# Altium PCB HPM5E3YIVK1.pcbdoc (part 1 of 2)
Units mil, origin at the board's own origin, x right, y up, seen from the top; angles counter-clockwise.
Board outline 3937 x 3149.7 mil, 6 copper layers (Top Layer, Inner1, Inner2, Inner3, Inner4, Bottom Layer), stack 60.7 mil thick; 242 components, 203 nets, 838 pads, 137 vias.
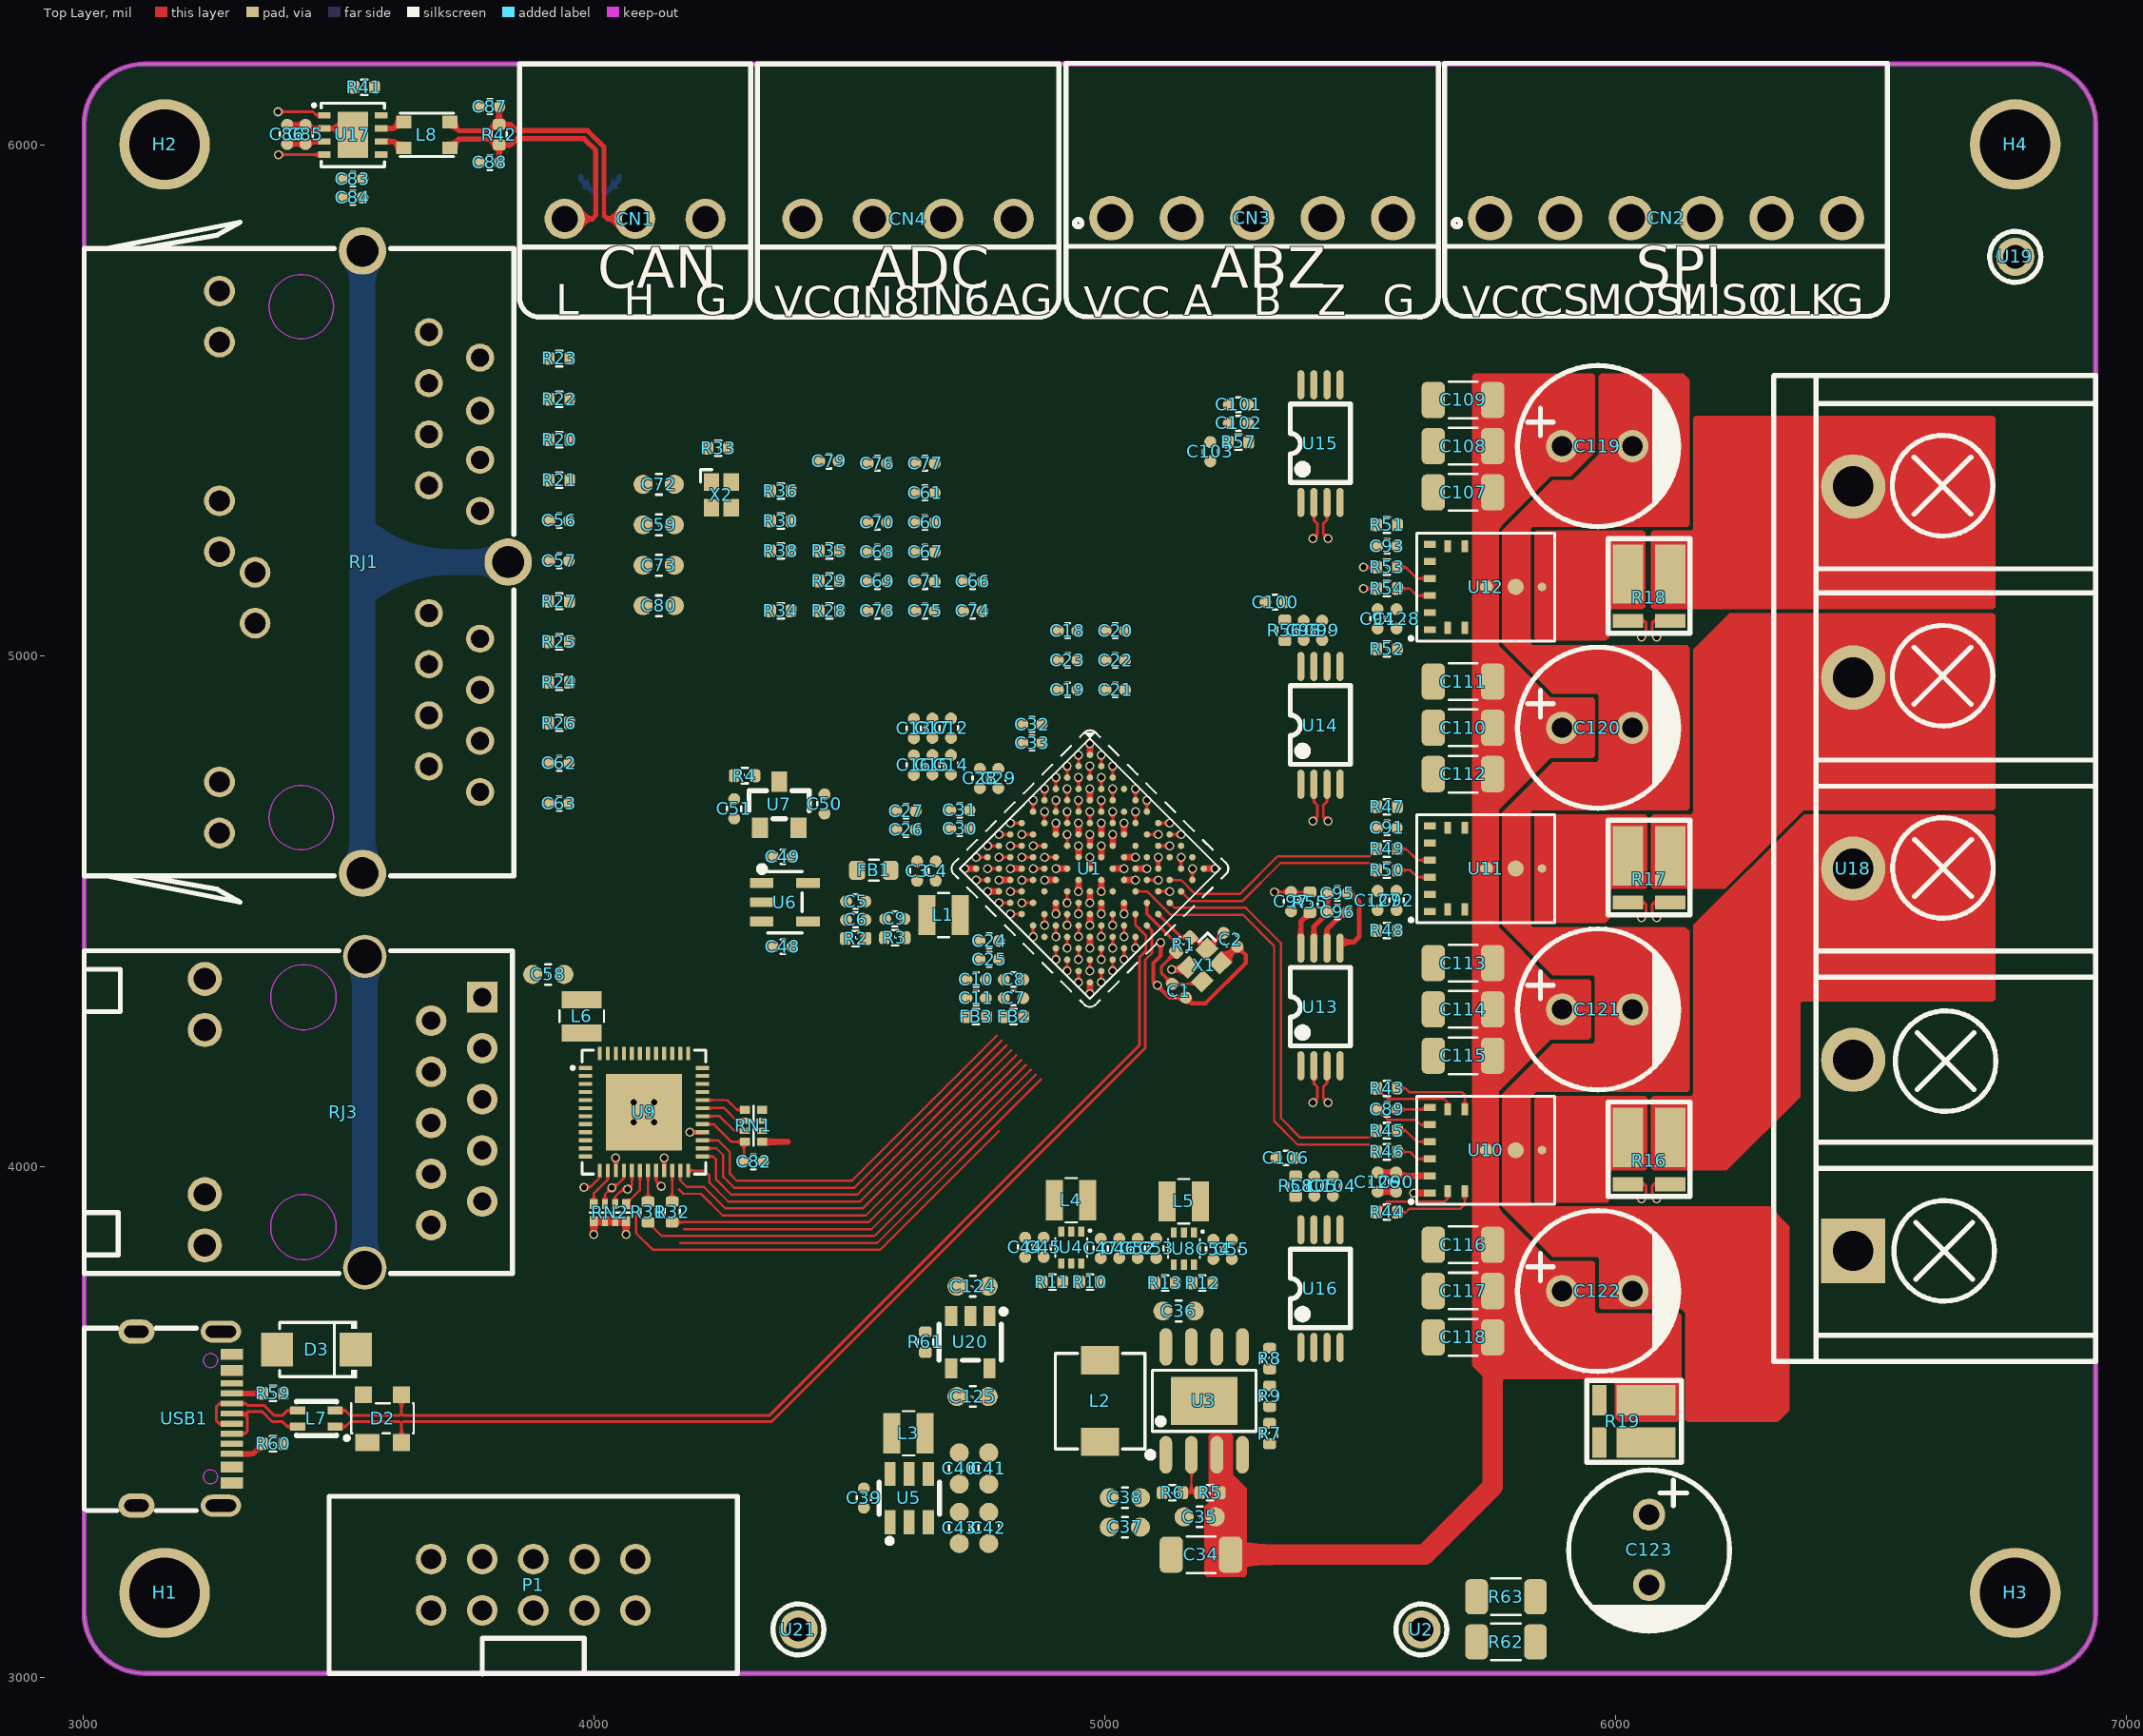
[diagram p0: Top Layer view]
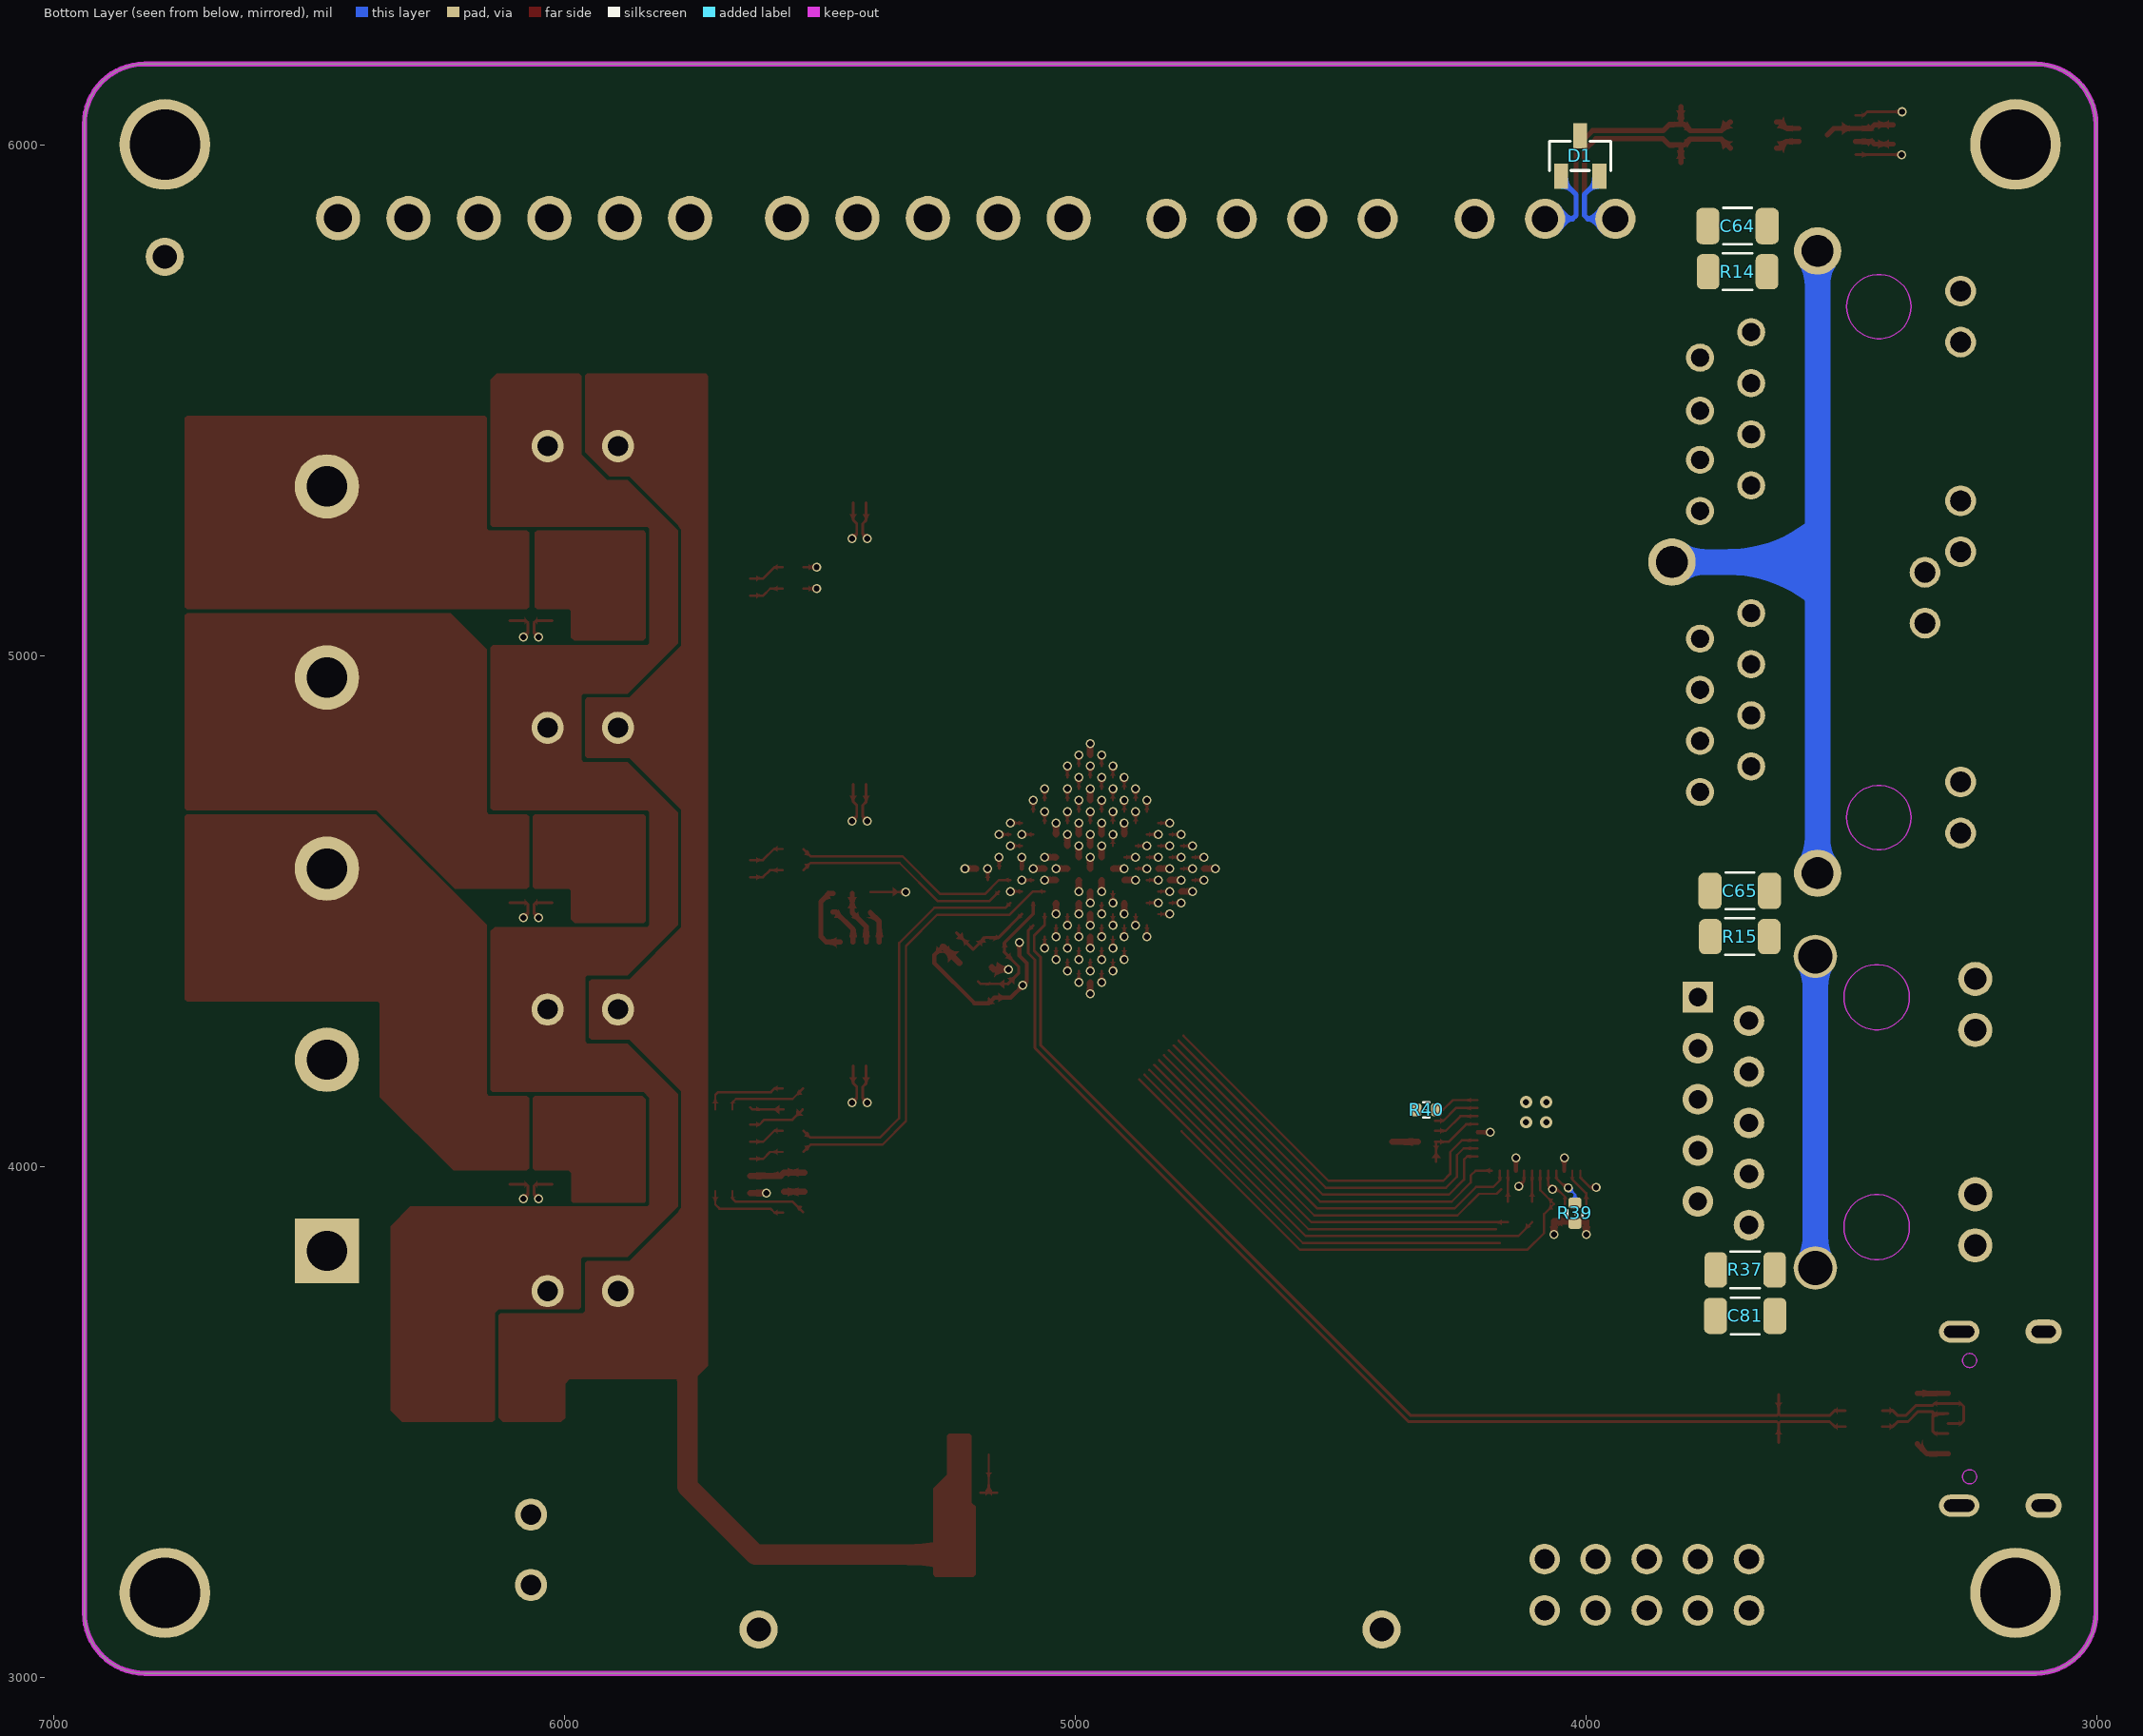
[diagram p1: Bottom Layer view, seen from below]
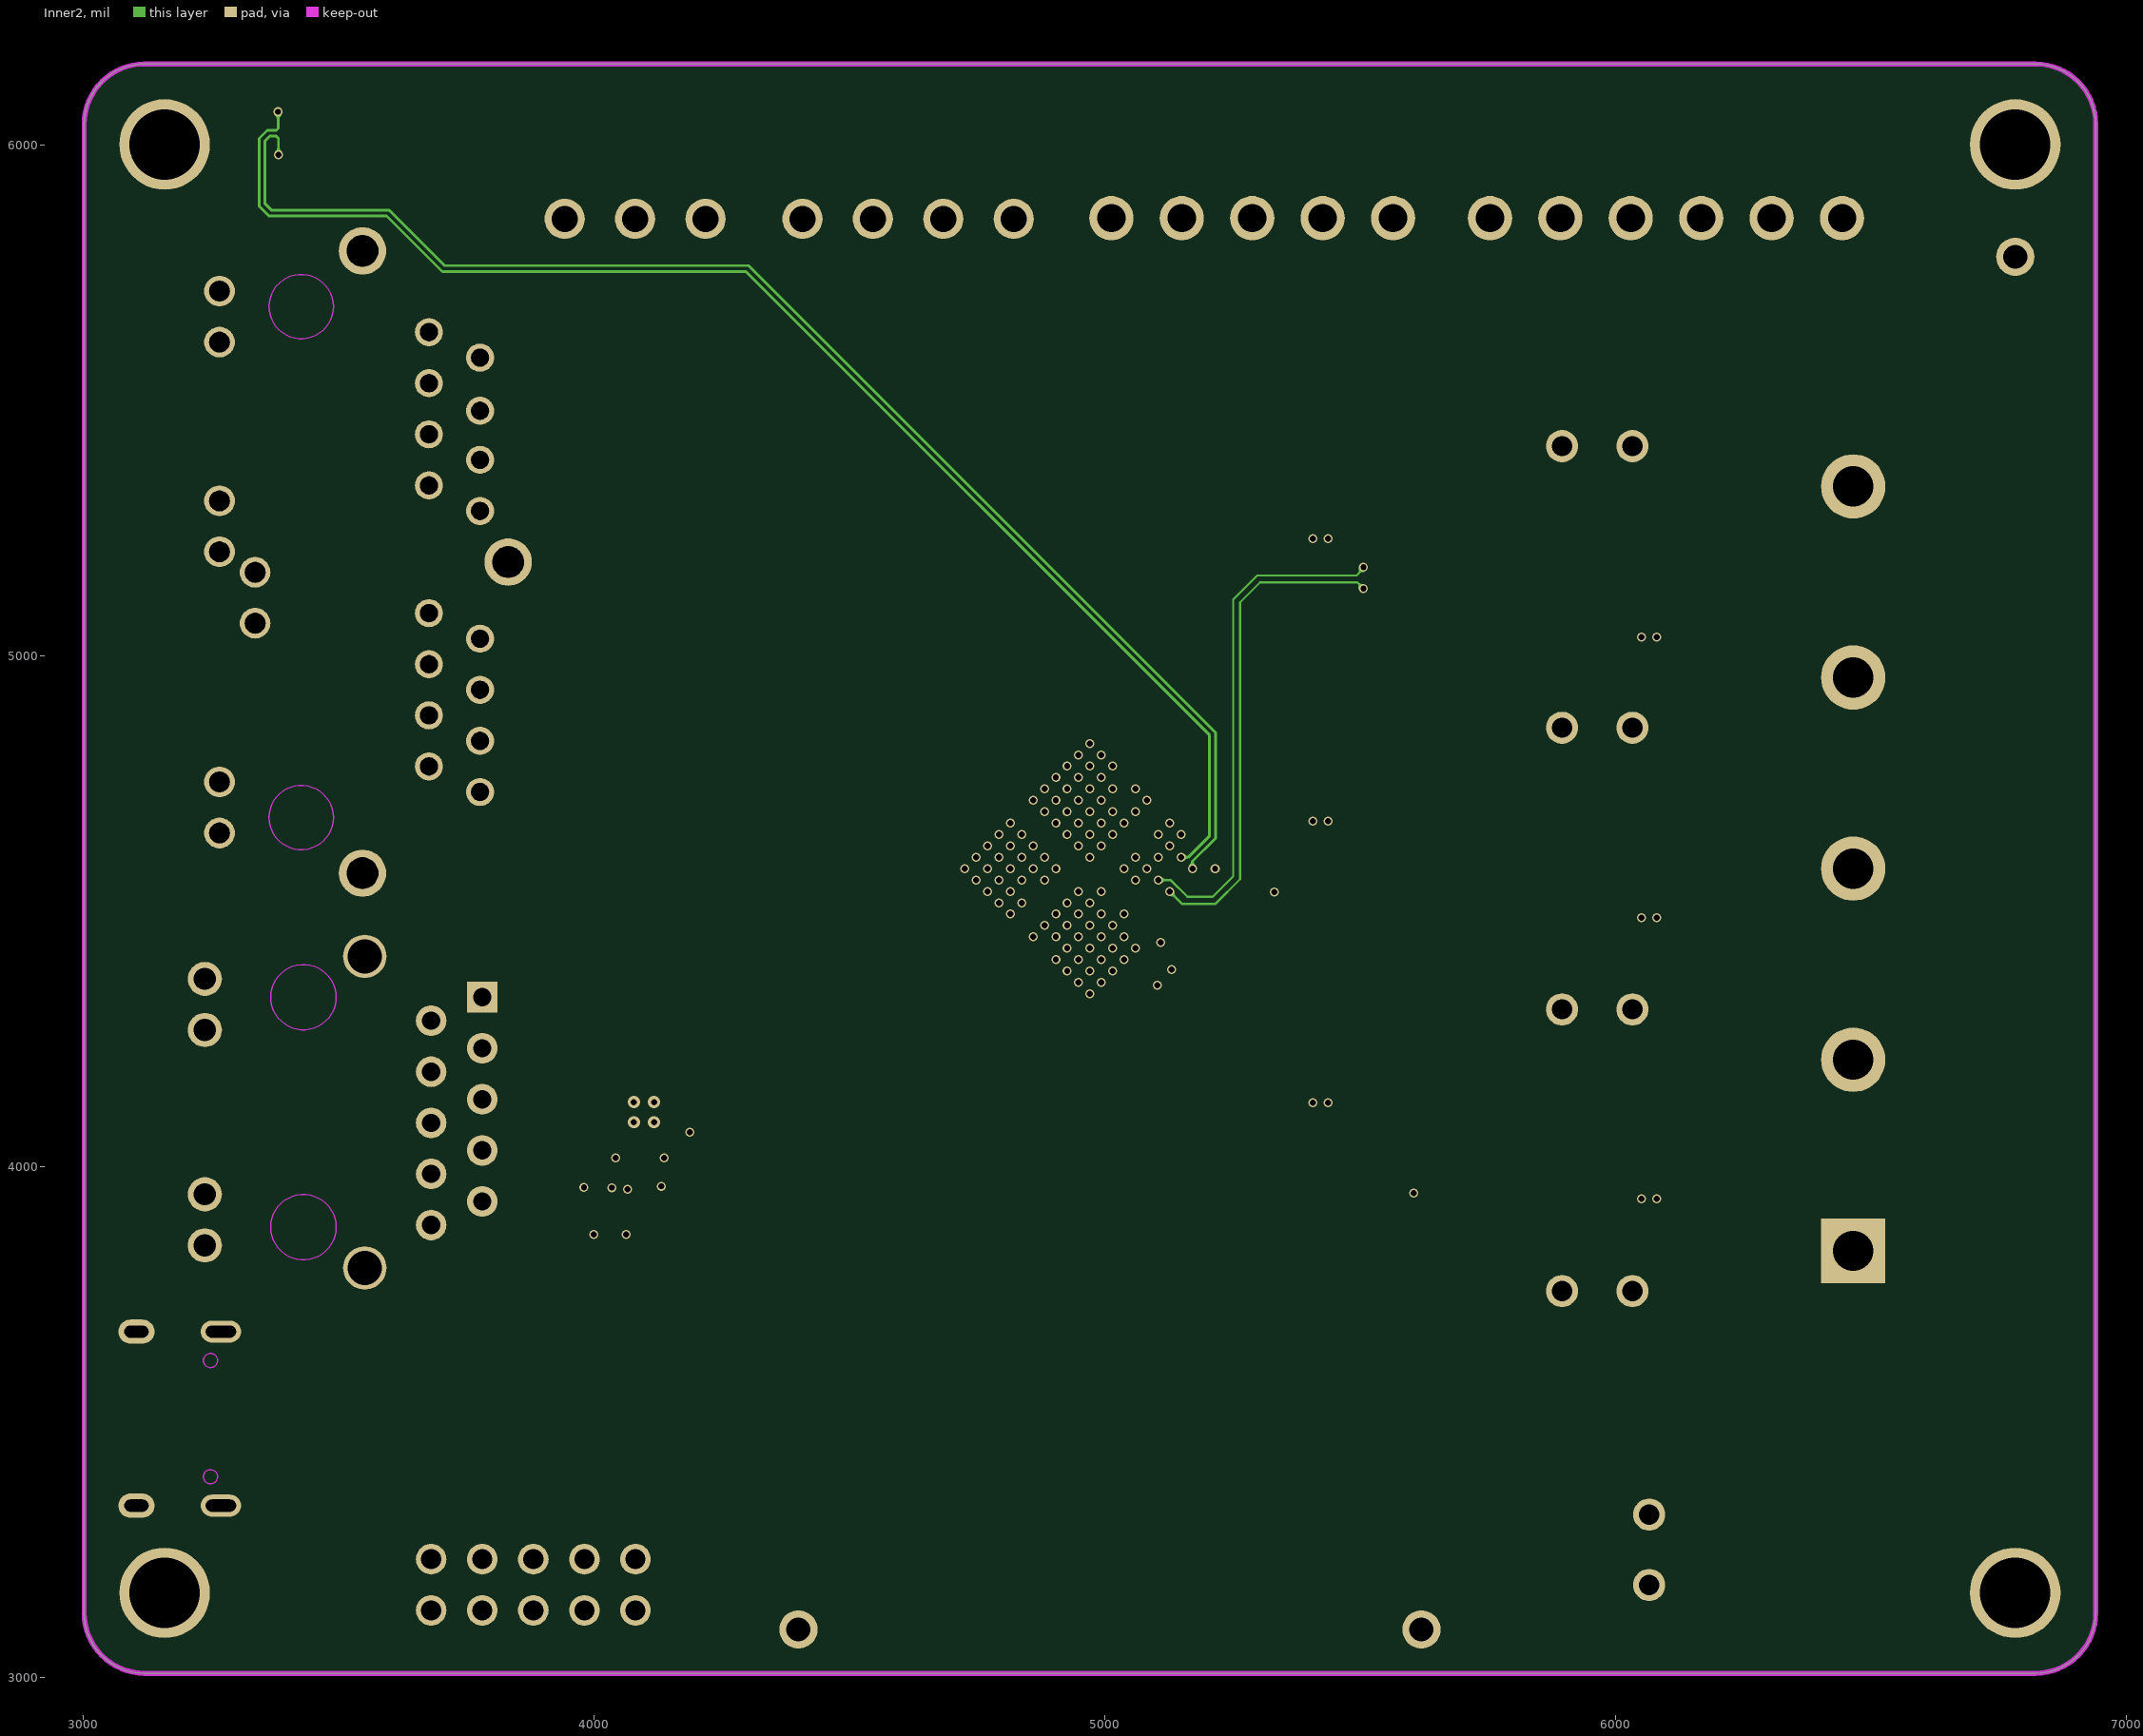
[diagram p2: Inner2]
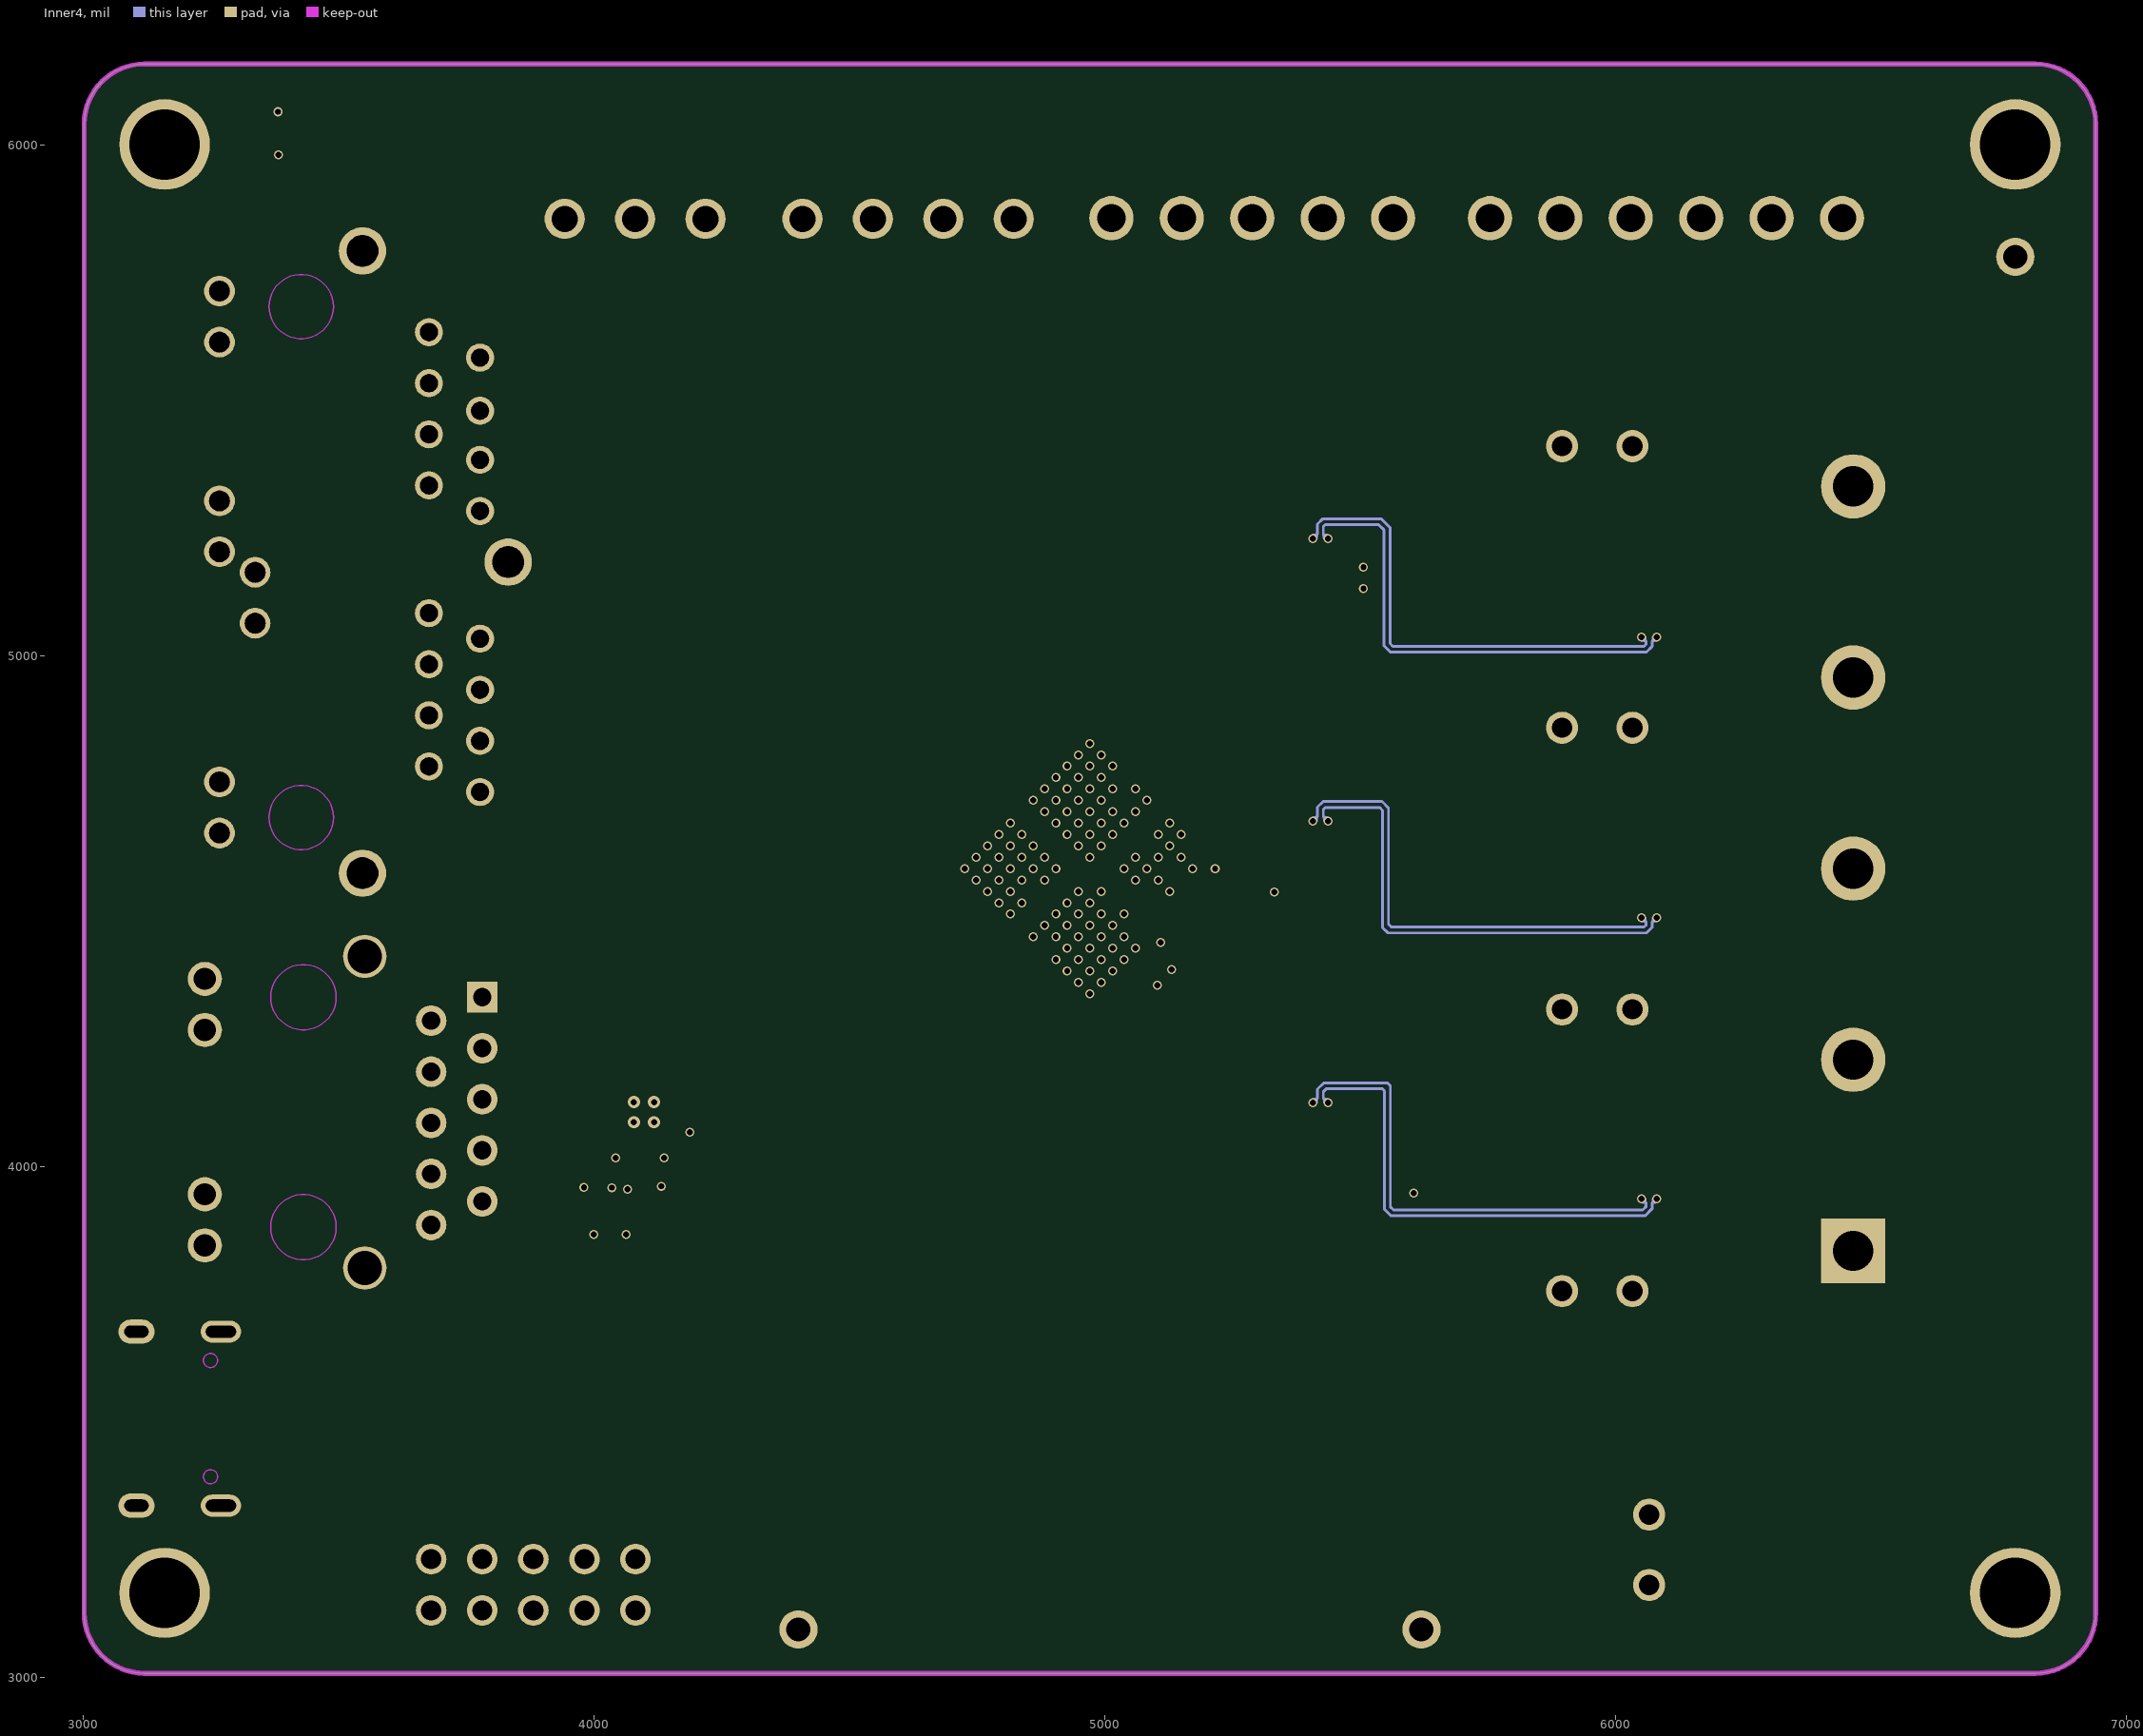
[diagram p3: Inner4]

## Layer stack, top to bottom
Top Layer: signal copper 1.4
Dielectric1: surface 3.9, 3313 RC57% 4.2mil, Dk 0
Inner1: signal copper 0.6
Dielectric2: surface 21.7, 0.55mm H/H No copper, Dk 0
Inner2: signal copper 0.6
Dielectric3: surface 4.3, 2116 RC54% 4.9mil, Dk 0
Inner3: signal copper 0.6
Dielectric4: surface 21.7, 0.55mm H/H No copper, Dk 0
Inner4: signal copper 0.6
Dielectric5: surface 3.9, 3313 RC57% 4.2mil, Dk 0
Bottom Layer: signal copper 1.4

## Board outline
3120.5,6158.6 6821.3,6158.6 cw(c6821.3,6040.4) 6939.4,6040.4 6939.4,3127.1 cw(c6821.3,3127.1) 6821.3,3008.9 3120.5,3008.9 cw(c3120.5,3127.1) 3002.4,3127.1 3002.4,6040.4 cw(c3120.5,6040.4)

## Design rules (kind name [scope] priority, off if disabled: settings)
BoardOutlineClearance copperThickness1oz [All] p0: genericclearance=10 ignorepadtopadclearanceinfootprint=FALSE except(0: Arc-SplitContinuation Track-SplitContinuation SMDPad-SplitContinuation THPad-SplitContinuation Via-SplitContinuation Fill-SplitContinuation Poly-SplitContinuation Region-SplitContinuation Text-SplitContinuation)
BoardOutlineClearance copperThickness2oz [All] p0: genericclearance=10 ignorepadtopadclearanceinfootprint=FALSE except(0: Arc-SplitContinuation Track-SplitContinuation SMDPad-SplitContinuation THPad-SplitContinuation Via-SplitContinuation Fill-SplitContinuation Poly-SplitContinuation Region-SplitContinuation Text-SplitContinuation)
BoardOutlineClearance otherClearance [All] p0: genericclearance=10 ignorepadtopadclearanceinfootprint=FALSE except(0: Arc-SplitContinuation Track-SplitContinuation SMDPad-SplitContinuation THPad-SplitContinuation Via-SplitContinuation Fill-SplitContinuation Poly-SplitContinuation Region-SplitContinuation Text-SplitContinuation)
Clearance copperThickness1oz [All] p1: gap=7 ignorepadtopadclearanceinfootprint=FALSE
Clearance copperThickness2oz [All] p1: gap=7 ignorepadtopadclearanceinfootprint=FALSE
Clearance otherClearance [All] p1: gap=7 ignorepadtopadclearanceinfootprint=FALSE
DiffPairsRouting differentialPair [All] p1: maxuncoupledlength=10 minlimit=6 maxlimit=Infinity mostfreqgap=6 toplayer_minwidth=5 toplayer_prefwidth=5.5 toplayer_maxwidth=100 bottomlayer_minwidth=5 bottomlayer_prefwidth=5.5 bottomlayer_maxwidth=100 midlayer1_minwidth=5 midlayer1_prefwidth=5.5 midlayer1_maxwidth=100 midlayer2_minwidth=5 midlayer2_prefwidth=5.5 midlayer2_maxwidth=100 midlayer3_minwidth=5 midlayer3_prefwidth=5.5 midlayer3_maxwidth=100 midlayer4_minwidth=5 midlayer4_prefwidth=5.5 midlayer4_maxwidth=100
PasteMaskExpansion pasteMaskExpansion [All] p1: expansion=0
PlaneConnect innerPlane [All] p1: planeconnectstyle=Relief reliefexpansion=20 reliefentries=4 reliefconductorwidth=10 reliefairgap=10
PolygonConnect copperRegion [All] p1: connectstyle=Relief reliefentries=4 reliefconductorwidth=10 polygonreliefangle="90 Angle" airgapwidth=10
RoutingVias viaSize [All] p1: viastyle="Through Hole" holewidth=12.0078 minholewidth=11.811 maxholewidth=248.0314 width=12.0078 minwidth=11.811 maxwidth=248.0314
SolderMaskExpansion solderMaskExpansion [IsVia] p1: useseparateexpansions=TRUE expansion=-1000 expansionbottom=-1000
SolderMaskExpansion solderMaskExpansion [All] p2: useseparateexpansions=TRUE expansion=2 expansionbottom=2
Width copperThickness1oz [All] p1: maxlimit=100 minlimit=4 preferedwidth=5
Width copperThickness2oz [All] p1: maxlimit=100 minlimit=8 preferedwidth=12

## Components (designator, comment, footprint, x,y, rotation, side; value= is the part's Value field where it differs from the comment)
C1 "" 03_HPM_Capacitance:C_0402_1005Metric#1 5145,4344.7 r315 top
C2 "" 03_HPM_Capacitance:C_0402_1005Metric#2 5245.8,4444.7 r315 top
C3 "" 03_HPM_Capacitance:C_0402_1005Metric#3 4632.7,4578.9 r90 top
C4 "" 03_HPM_Capacitance:C_0402_1005Metric#3 4669,4578.9 r90 top
C5 "" 03_HPM_Capacitance:C_0402_1005Metric#3 4512.5,4519.5 r180 top
C6 "" 03_HPM_Capacitance:C_0402_1005Metric#3 4512.5,4483.5 r180 top
C7 "" 03_HPM_Capacitance:C_0402_1005Metric#3 4821.3,4330.4 r0 top
C8 "" 03_HPM_Capacitance:C_0402_1005Metric#3 4821.3,4366.6 r0 top
C9 "" 03_HPM_Capacitance:C_0402_1005Metric#3 4589,4485.5 r0 top
C10 "" 03_HPM_Capacitance:C_0402_1005Metric#3 4748.2,4366.6 r180 top
C11 "" 03_HPM_Capacitance:C_0402_1005Metric#3 4748.2,4330.4 r180 top
C12 "" 03_HPM_Capacitance:C_0402_1005Metric#3 4698.9,4858.6 r270 top
C13 "" 03_HPM_Capacitance:C_0402_1005Metric#3 4626.2,4857.9 r270 top
C14 "" 03_HPM_Capacitance:C_0402_1005Metric#3 4698.9,4786.9 r270 top
C15 "" 03_HPM_Capacitance:C_0402_1005Metric#3 4662.6,4786.9 r270 top
C16 "" 03_HPM_Capacitance:C_0402_1005Metric#3 4626.2,4786.2 r270 top
C17 "" 03_HPM_Capacitance:C_0402_1005Metric#3 4662.6,4858.6 r270 top
C18 "" 03_HPM_Capacitance:C_0402_1005Metric#3 4927.3,5049.3 r0 top
C19 "" 03_HPM_Capacitance:C_0402_1005Metric#3 4927.3,4933.6 r0 top
C20 "" 03_HPM_Capacitance:C_0402_1005Metric#3 5020.6,5049.3 r0 top
C21 "" 03_HPM_Capacitance:C_0402_1005Metric#3 5020.6,4933.6 r0 top
C22 "" 03_HPM_Capacitance:C_0402_1005Metric#3 5020.6,4991.4 r0 top
C23 "" 03_HPM_Capacitance:C_0402_1005Metric#3 4927.3,4991.4 r0 top
C24 "" 03_HPM_Capacitance:C_0402_1005Metric#3 4773.8,4442.4 r0 top
C25 "" 03_HPM_Capacitance:C_0402_1005Metric#3 4773.8,4406.2 r0 top
C26 "" 03_HPM_Capacitance:C_0402_1005Metric#3 4610.9,4660 r180 top
C27 "" 03_HPM_Capacitance:C_0402_1005Metric#3 4610.9,4696.2 r180 top
C28 "" 03_HPM_Capacitance:C_0402_1005Metric#3 4755.4,4760.1 r90 top
C29 "" 03_HPM_Capacitance:C_0402_1005Metric#3 4791.6,4760.1 r90 top
C30 "" 03_HPM_Capacitance:C_0402_1005Metric#3 4716.3,4661.7 r180 top
C31 "" 03_HPM_Capacitance:C_0402_1005Metric#3 4716.3,4697.9 r180 top
C32 "" 03_HPM_Capacitance:C_0402_1005Metric#3 4857.6,4865.9 r0 top
C33 "" 03_HPM_Capacitance:C_0402_1005Metric#3 4857.6,4829.7 r0 top
C34 "" 03_HPM_Capacitance:C_1206_3216Metric#1 5188.1,3241.2 r180 top
C35 "" 03_HPM_Capacitance:C_0603_1608Metric#1 5185.6,3315.1 r180 top
C36 "" 03_HPM_Capacitance:C_0603_1608Metric#2 5144.3,3717.9 r0 top
C37 "" 03_HPM_Capacitance:C_0603_1608Metric#1 5039.3,3294.9 r0 top
C38 "" 03_HPM_Capacitance:C_0603_1608Metric#1 5039.3,3352.6 r0 top
C39 "" 03_HPM_Capacitance:C_0402_1005Metric#3 4528.4,3352 r270 top
C40 "" 03_HPM_Capacitance:C_0603_1608Metric#1 4715.2,3409.8 r270 top
C41 "" 03_HPM_Capacitance:C_0603_1608Metric#3 4772.8,3409.8 r270 top
C42 "" 03_HPM_Capacitance:C_0603_1608Metric#1 4772.8,3293.3 r270 top
C43 "" 03_HPM_Capacitance:C_0603_1608Metric#1 4715.2,3293.3 r270 top
C44 "" 03_HPM_Capacitance:C_0402_1005Metric#3 4844.1,3842.6 r270 top
C45 "" 03_HPM_Capacitance:C_0402_1005Metric#3 4880.3,3842.6 r270 top
C46 "" 03_HPM_Capacitance:C_0402_1005Metric#3 5028.2,3840.5 r90 top
C47 "" 03_HPM_Capacitance:C_0402_1005Metric#3 4992,3840.5 r90 top
C48 "" 03_HPM_Capacitance:C_0402_1005Metric#3 4369.6,4430.8 r0 top
C49 "" 03_HPM_Capacitance:C_0402_1005Metric#3 4369.6,4606.8 r180 top
C50 "" 03_HPM_Capacitance:C_0402_1005Metric#3 4451.4,4710.2 r90 top
C51 "" 03_HPM_Capacitance:C_0402_1005Metric#3 4274.7,4700.8 r90 top
C52 "" 03_HPM_Capacitance:C_0402_1005Metric#3 5064.4,3840.5 r270 top
C53 "" 03_HPM_Capacitance:C_0402_1005Metric#3 5100.7,3840.5 r270 top
C54 "" 03_HPM_Capacitance:C_0402_1005Metric#3 5212.4,3838.5 r90 top
C55 "" 03_HPM_Capacitance:C_0402_1005Metric#3 5248.6,3838.5 r90 top
C56 "" 03_HPM_Capacitance:C_0402_1005Metric#3 3931.9,5264.7 r0 top
C57 "" 03_HPM_Capacitance:C_0402_1005Metric#3 3931.9,5186.1 r0 top
C58 "" 03_HPM_Capacitance:C_0603_1608Metric#2 3910.9,4376.6 r180 top
C59 "" 03_HPM_Capacitance:C_0603_1608Metric#1 4127,5256.5 r180 top
C60 "" 03_HPM_Capacitance:C_0402_1005Metric#3 4648.2,5261.3 r180 top
C61 "" 03_HPM_Capacitance:C_0402_1005Metric#3 4648.2,5319.1 r180 top
C62 "" 03_HPM_Capacitance:C_0402_1005Metric#3 3931.9,4789.8 r0 top
C63 "" 03_HPM_Capacitance:C_0402_1005Metric#3 3931.9,4711.2 r0 top
C64 "" 03_HPM_Capacitance:C_1206_3216Metric#2 3703.9,5841.1 r0 bottom
C65 "" 03_HPM_Capacitance:C_1206_3216Metric#3 3699.5,4540.1 r0 bottom
C66 "" 03_HPM_Capacitance:C_0402_1005Metric#3 4741.6,5145.5 r180 top
C67 "" 03_HPM_Capacitance:C_0402_1005Metric#3 4648.2,5203.4 r180 top
C68 "" 03_HPM_Capacitance:C_0402_1005Metric#3 4554.9,5203.4 r180 top
C69 "" 03_HPM_Capacitance:C_0402_1005Metric#3 4554.9,5145.5 r180 top
C70 "" 03_HPM_Capacitance:C_0402_1005Metric#3 4554.9,5261.3 r180 top
C71 "" 03_HPM_Capacitance:C_0402_1005Metric#3 4648.2,5145.5 r180 top
C72 "" 03_HPM_Capacitance:C_0603_1608Metric#1 4127,5335.7 r180 top
C73 "" 03_HPM_Capacitance:C_0603_1608Metric#1 4127,5177.4 r180 top
C74 "" 03_HPM_Capacitance:C_0402_1005Metric#3 4741.6,5087.6 r180 top
C75 "" 03_HPM_Capacitance:C_0402_1005Metric#3 4648.2,5087.6 r180 top
C76 "" 03_HPM_Capacitance:C_0402_1005Metric#3 4554.9,5377 r180 top
C77 "" 03_HPM_Capacitance:C_0402_1005Metric#3 4648.2,5377 r180 top
C78 "" 03_HPM_Capacitance:C_0402_1005Metric#3 4554.9,5087.6 r180 top
C79 "" 03_HPM_Capacitance:C_0402_1005Metric#3 4460.1,5380.9 r180 top
C80 "" 03_HPM_Capacitance:C_0603_1608Metric#1 4127,5098.3 r0 top
C81 "" 03_HPM_Capacitance:C_1206_3216Metric#2 3688.9,3708.4 r0 bottom
C82 "" 03_HPM_Capacitance:C_0402_1005Metric#3 4312.5,4009.9 r180 top
C83 "" 03_HPM_Capacitance:C_0402_1005Metric#3 3528.3,5933.4 r180 top
C84 "" 03_HPM_Capacitance:C_0402_1005Metric#3 3528.3,5896.8 r180 top
C85 "" 03_HPM_Capacitance:C_0402_1005Metric#3 3435.8,6020.6 r90 top
C86 "" 03_HPM_Capacitance:C_0402_1005Metric#3 3399.6,6020.6 r90 top
C87 "" 03_HPM_Capacitance:C_0402_1005Metric#3 3796,6075 r0 top
C88 "" 03_HPM_Capacitance:C_0402_1005Metric#3 3796,5965.4 r0 top
C89 "" 03_HPM_Capacitance:C_0402_1005Metric#3 5552.4,4112.4 r0 top
C90 "" 03_HPM_Capacitance:C_0402_1005Metric#3 5570.2,3970.2 r270 top
C91 "" 03_HPM_Capacitance:C_0402_1005Metric#3 5552.4,4663.5 r0 top
C92 "" 03_HPM_Capacitance:C_0402_1005Metric#3 5570.9,4521.4 r270 top
C93 "" 03_HPM_Capacitance:C_0402_1005Metric#3 5552.4,5214.7 r0 top
C94 "" 03_HPM_Capacitance:C_0402_1005Metric#3 5533.9,5072.6 r270 top
C95 "" 03_HPM_Capacitance:C_0402_1005Metric#3 5455.5,4535.2 r180 top
C96 "" 03_HPM_Capacitance:C_0402_1005Metric#3 5455.5,4498.8 r180 top
C97 "" 03_HPM_Capacitance:C_0402_1005Metric#4 5364.6,4519.1 r270 top
C98 "" 03_HPM_Capacitance:C_0402_1005Metric#3 5389.2,5050.1 r90 top
C99 "" 03_HPM_Capacitance:C_0402_1005Metric#3 5425.3,5050.1 r90 top
C100 "" 03_HPM_Capacitance:C_0402_1005Metric#3 5333.5,5105.2 r180 top
C101 "" 03_HPM_Capacitance:C_0402_1005Metric#5 5261.5,5491.6 r180 top
C102 "" 03_HPM_Capacitance:C_0402_1005Metric#5 5261.5,5455.4 r180 top
C103 "" 03_HPM_Capacitance:C_0402_1005Metric#3 5206.4,5399.7 r270 top
C104 "" 03_HPM_Capacitance:C_0402_1005Metric#3 5446.2,3962.3 r90 top
C105 "" 03_HPM_Capacitance:C_0402_1005Metric#3 5410.1,3962.3 r90 top
C106 "" 03_HPM_Capacitance:C_0402_1005Metric#3 5354.4,4017.4 r180 top
C107 "" 03_HPM_Capacitance:C_1206_3216Metric#4 5701,5319.9 r0 top
C108 "" 03_HPM_Capacitance:C_1206_3216Metric#4 5701,5410.5 r0 top
C109 "" 03_HPM_Capacitance:C_1206_3216Metric#4 5701,5501 r0 top
C110 "" 03_HPM_Capacitance:C_1206_3216Metric#4 5701,4859.3 r0 top
C111 "" 03_HPM_Capacitance:C_1206_3216Metric#4 5701,4949.8 r0 top
C112 "" 03_HPM_Capacitance:C_1206_3216Metric#4 5701,4768.7 r0 top
C113 "" 03_HPM_Capacitance:C_1206_3216Metric#4 5701,4398.6 r0 top
C114 "" 03_HPM_Capacitance:C_1206_3216Metric#4 5701,4308.2 r0 top
C115 "" 03_HPM_Capacitance:C_1206_3216Metric#4 5701,4217.5 r0 top
C116 "" 03_HPM_Capacitance:C_1206_3216Metric#4 5701,3847.4 r0 top
C117 "" 03_HPM_Capacitance:C_1206_3216Metric#4 5701,3757 r0 top
C118 "" 03_HPM_Capacitance:C_1206_3216Metric#4 5701,3666.3 r0 top
C119 "470uF" CAP-TH_BD8.0-P3.50-D0.6-FD 5963.7,5410.5 r0 top
C120 "470uF" CAP-TH_BD8.0-P3.50-D0.6-FD 5963.7,4859.4 r0 top
C121 "470uF" CAP-TH_BD8.0-P3.50-D0.6-FD 5963.7,4308.2 r0 top
C122 "470uF" CAP-TH_BD8.0-P3.50-D0.6-FD 5963.7,3757 r0 top
C123 "470uF" CAP-TH_BD8.0-P3.50-D0.6-FD 6065.4,3250.7 r270 top
C124 "" 03_HPM_Capacitance:C_0603_1608Metric#1 4741.3,3766.3 r180 top
C125 "" 03_HPM_Capacitance:C_0603_1608Metric#1 4741.3,3550.5 r180 top
C126 "" 03_HPM_Capacitance:C_0402_1005Metric#3 5533.9,3970.2 r270 top
C127 "" 03_HPM_Capacitance:C_0402_1005Metric#3 5533.9,4521.4 r270 top
C128 "" 03_HPM_Capacitance:C_0402_1005Metric#3 5570.9,5072.6 r270 top
CN1 "XY2500R-G-3.5-3P" CONN-TH_XY2500R-G-3.5-3P 4080.7,5855.3 r180 top locked
CN2 "XY2500R-G-3.5-6P" CONN-TH_XY2500R-G-3.5-6P 6098.3,5856.8 r0 top locked
CN3 "XY2500R-G-3.5-5P" CONN-TH_XY2500R-G-3.5-5P 5288.5,5856.8 r0 top locked
CN4 "XY2500R-G-3.5-4P" CONN-TH_XY2500R-G-3.5-4P 4615,5855.3 r180 top locked
D1 "NUP2105LT1G" SOT-23-3_L2.9-W1.3-P1.90-LS2.4-BL-2 4011.8,5978.4 r180 bottom
D2 "PRTR5V0U2X" SOT-143-4_L2.9-W1.3-P1.92-LS2.4-BL 3586.1,3507.4 r0 top
D3 "SS34F" SMAF_L3.5-W2.6-LS4.7-RD-1 3456.9,3642.5 r180 top
FB1 "" 02_HPM_Resistor:R_0603_1608Metric 4547.8,4580.4 r180 top
FB2 "100Ω@120MHz_1.2A" 02_HPM_Resistor:R_0402_1005Metric#1 4821.3,4293.7 r0 top
FB3 "100Ω@120MHz_1.2A" 02_HPM_Resistor:R_0402_1005Metric#1 4748.2,4293.7 r0 top
H1 "01-HPM-Peripheral_MountingHole_Pad" 01_HPM_Peripheral:FIX1 3159.9,3166.4 r0 top
H2 "01-HPM-Peripheral_MountingHole_Pad" 01_HPM_Peripheral:FIX1 3159.9,6001.1 r0 top
H3 "01-HPM-Peripheral_MountingHole_Pad" 01_HPM_Peripheral:FIX1 6781.9,3166.4 r0 top
H4 "01-HPM-Peripheral_MountingHole_Pad" 01_HPM_Peripheral:FIX1 6781.9,6001.1 r0 top
L1 "4.7uH" IND-SMD_L2.5-W2.0-VLS252012CX-150M#1 4684.4,4492.8 r0 top
L2 "15uH" IND-SMD_L4.6-W4.2_SMMS0420 4990.9,3541.6 r90 top
L3 "4.7uH" IND-SMD_L2.5-W2.0-VLS252012CX-150M#1 4615.8,3478.5 r0 top
L4 "1uH" IND-SMD_L2.5-W2.0-VLS252012CX-150M#2 4934.2,3934.6 r0 top
L5 "1uH" IND-SMD_L2.5-W2.0-VLS252012CX-150M#1 5154.6,3932.6 r0 top
L6 "4.7uH" IND-SMD_L2.5-W2.0-VLS252012CX-150M#2 3976.2,4294.8 r90 top
L7 "DLW21SN900SQ2L" FILTER-SMD_4P-L2.0-W1.2-BL_DLW21H 3456.9,3507.4 r270 top
L8 "ACM2520-301-2P-T002" FILTER-SMD_4P-L2.5-W2.0-BL 3672.9,6019.6 r0 top
P1 "2.54-2*5P简牛" IDC-TH_10P-P2.54_C5665 3881.5,3182.2 r0 top
R1 "" 02_HPM_Resistor:R_0402_1005Metric#1 5153.7,4435 r45 top
R2 "" 02_HPM_Resistor:R_0402_1005Metric#1 4512.5,4446.9 r0 top
R3 "" 02_HPM_Resistor:R_0402_1005Metric#1 4589,4448.5 r0 top
R4 "" 02_HPM_Resistor:R_0402_1005Metric#2 4294.9,4765.5 r0 top
R5 "" 02_HPM_Resistor:R_0402_1005Metric#3 5205.7,3362.3 r180 top
R6 "" 02_HPM_Resistor:R_0402_1005Metric#1 5132.5,3362.3 r180 top
R7 "" 02_HPM_Resistor:R_0402_1005Metric#1 5322.5,3477.9 r90 top
R8 "" 02_HPM_Resistor:R_0402_1005Metric#1 5322.9,3624.8 r90 top
R9 "" 02_HPM_Resistor:R_0402_1005Metric#2 5322.9,3551.2 r90 top
R10 "" 02_HPM_Resistor:R_0402_1005Metric#1 4970.8,3775 r180 top
R11 "" 02_HPM_Resistor:R_0402_1005Metric#1 4897.5,3775 r0 top
R12 "" 02_HPM_Resistor:R_0402_1005Metric#1 5191.2,3772.9 r180 top
R13 "" 02_HPM_Resistor:R_0402_1005Metric#1 5117.9,3772.9 r0 top
R14 "" 02_HPM_Resistor:R_1206_3216Metric#1 3703.9,5751.8 r180 bottom
R15 "" 02_HPM_Resistor:R_1206_3216Metric#2 3699.5,4450.7 r180 bottom
R16 "0.5mΩ" RES-SMD_4P-L3.0-W3.8_HOBB1216#1 6065.2,4012 r180 top
R17 "0.5mΩ" RES-SMD_4P-L3.0-W3.8_HOBB1216#2 6065.2,4563.2 r180 top
R18 "0.5mΩ" RES-SMD_4P-L3.0-W3.8_HOBB1216#2 6065.2,5114.4 r180 top
R19 "0.5mΩ" RES-SMD_4P-L3.0-W3.8_HOBB1216#1 6013.5,3502 r90 top
R20 "" 02_HPM_Resistor:R_0402_1005Metric#1 3932.7,5423.1 r0 top
R21 "" 02_HPM_Resistor:R_0402_1005Metric#1 3932.7,5343.7 r0 top
R22 "" 02_HPM_Resistor:R_0402_1005Metric#1 3932.7,5502.5 r0 top
R23 "" 02_HPM_Resistor:R_0402_1005Metric#1 3932.7,5581.9 r0 top
R24 "" 02_HPM_Resistor:R_0402_1005Metric#1 3931.9,4948.2 r0 top
R25 "" 02_HPM_Resistor:R_0402_1005Metric#1 3931.9,5027.6 r0 top
R26 "" 02_HPM_Resistor:R_0402_1005Metric#1 3931.9,4868.8 r0 top
R27 "" 02_HPM_Resistor:R_0402_1005Metric#1 3931.9,5107 r0 top
R28 "" 02_HPM_Resistor:R_0402_1005Metric#3 4460.8,5088 r180 top
R29 "" 02_HPM_Resistor:R_0402_1005Metric#3 4460.8,5146.7 r180 top
R30 "" 02_HPM_Resistor:R_0402_1005Metric#2 4366,5264 r180 top
R31 "" 02_HPM_Resistor:R_0402_1005Metric#3 4106,3911.7 r90 top
R32 "" 02_HPM_Resistor:R_0402_1005Metric#3 4153.2,3911.7 r90 top
R33 "" 02_HPM_Resistor:R_0402_1005Metric#3 4243.5,5406.5 r180 top
R34 "" 02_HPM_Resistor:R_0402_1005Metric#2 4366,5088 r180 top
R35 "" 02_HPM_Resistor:R_0402_1005Metric#3 4460.8,5205.3 r180 top
R36 "" 02_HPM_Resistor:R_0402_1005Metric#2 4366,5322.7 r180 top
R37 "" 02_HPM_Resistor:R_1206_3216Metric#1 3688.9,3798.5 r180 bottom
R38 "" 02_HPM_Resistor:R_0402_1005Metric#2 4366,5205.3 r180 top
R39 "" 02_HPM_Resistor:R_0402_1005Metric#3 4022.1,3909.2 r270 bottom
R40 "" 02_HPM_Resistor:R_0402_1005Metric#1 4313,4111.7 r0 bottom
R41 "" 02_HPM_Resistor:R_0402_1005Metric#2 3550.5,6113.2 r0 top
R42 "" 02_HPM_Resistor:R_0402_1005Metric#1 3814.9,6020 r270 top
R43 "" 02_HPM_Resistor:R_0402_1005Metric#1 5552.4,4153.7 r0 top
R44 "" 02_HPM_Resistor:R_0402_1005Metric#1 5552.4,3911.2 r0 top
R45 "" 02_HPM_Resistor:R_0402_1005Metric#1 5552.4,4071 r180 top
R46 "" 02_HPM_Resistor:R_0402_1005Metric#1 5552.4,4029.3 r180 top
R47 "" 02_HPM_Resistor:R_0402_1005Metric#1 5552.4,4704.9 r0 top
R48 "" 02_HPM_Resistor:R_0402_1005Metric#1 5552.4,4462.4 r180 top
R49 "" 02_HPM_Resistor:R_0402_1005Metric#1 5552.4,4622.2 r180 top
R50 "" 02_HPM_Resistor:R_0402_1005Metric#1 5552.4,4580.5 r180 top
R51 "" 02_HPM_Resistor:R_0402_1005Metric#1 5552.4,5256.1 r0 top
R52 "" 02_HPM_Resistor:R_0402_1005Metric#1 5552.4,5013.6 r180 top
R53 "" 02_HPM_Resistor:R_0402_1005Metric#1 5552.4,5173.4 r180 top
R54 "" 02_HPM_Resistor:R_0402_1005Metric#1 5552.4,5131.7 r180 top
R55 "" 02_HPM_Resistor:R_0402_1005Metric#2 5401.2,4517.9 r270 top
R56 "" 02_HPM_Resistor:R_0402_1005Metric#1 5352.4,5050.1 r270 top
R57 "" 02_HPM_Resistor:R_0402_1005Metric#2 5261.5,5418.6 r0 top
R58 "" 02_HPM_Resistor:R_0402_1005Metric#1 5373.3,3962.3 r270 top
R59 "" 02_HPM_Resistor:R_0402_1005Metric#1 3372.4,3556.6 r180 top
R60 "" 02_HPM_Resistor:R_0402_1005Metric#1 3372.4,3458.1 r180 top
R61 "" 02_HPM_Resistor:R_0402_1005Metric#3 4649,3656.9 r270 top
R62 "" 02_HPM_Resistor:R_1206_3216Metric#3 5785.2,3070.3 r180 top
R63 "" 02_HPM_Resistor:R_1206_3216Metric#3 5785.2,3158.5 r180 top
RJ1 "J8064D628ANL" RJ45-TH_J8064D628ANL 3549.8,5183.7 r270 top locked
RJ3 "HR911130A" RJ45-TH_HR911130A 3510,4107.1 r90 top locked
RN1 "0Ω" RES-ARRAY-SMD_8P-L2.0-W1.0-BL_CN24XXXX 4312.5,4080.5 r270 top
RN2 "0Ω" RES-ARRAY-SMD_8P-L2.0-W1.0-BL_CN24XXXX 4031.6,3910.5 r180 top
U1 "" CABGA-121_L9.0-W9.0-R11-C11-P0.80-TL 4970.9,4583.7 r315 top
U2 "RH-5000" TEST-TH_BD2.54-P1.4_RED 5619.6,3094.7 r0 top
U3 "LMR38020FDDAR" ESOP-8_L4.9-W3.9-P1.27-LS6.0-BL-EP-1 5194.3,3542.1 r0 top
U4 "TPS62A02DRLR" SOT-563_L1.6-W1.2-P0.50-LS1.6-TL#1 4934.3,3842.2 r270 top
U5 "AP63205WU-7" TSOT-23-6_L2.9-W1.6-P0.95-LS2.8-BL 4617.2,3351.8 r0 top
U6 "RT9013-33GB" SOT-23-5_L3.0-W1.7-P0.95-LS2.8-BL 4374,4517.9 r270 top
U7 "NCP51460SN33T1G" SOT-23_L2.9-W1.3-P1.90-LS2.4-BR 4362.8,4708.8 r270 top
U8 "TPS62A02DRLR" SOT-563_L1.6-W1.2-P0.50-LS1.6-TL#2 5154.7,3840.2 r270 top
U9 "RTL8211E-VB-CG" QFN-48_L6.0-W6.0-P0.40-BL-EP3.8 4098.1,4107.1 r270 top
U10 "ISG3204LA" LGA-25_L6.5-W5.0-P0.85-TL#1 5745.8,4032.6 r90 top
U11 "ISG3204LA" LGA-25_L6.5-W5.0-P0.85-TL#2 5745.8,4583.8 r90 top
U12 "ISG3204LA" LGA-25_L6.5-W5.0-P0.85-TL#3 5745.8,5134.9 r90 top
U13 "INA240A1PWR" TSSOP-8_L4.4-W3.0-P0.65-LS6.4-BL#1 5422,4313 r0 top
U14 "INA240A1PWR" TSSOP-8_L4.4-W3.0-P0.65-LS6.4-BL#2 5422,4864.2 r0 top
U15 "INA240A1PWR" TSSOP-8_L4.4-W3.0-P0.65-LS6.4-BL#2 5422,5415.4 r0 top
U16 "INA240A1PWR" TSSOP-8_L4.4-W3.0-P0.65-LS6.4-BL#3 5422,3761.8 r0 top
U17 "SIT1042AQTK/3" TDFN-8_L3.0-W3.0-P0.65-BL-EP2.3 3528.3,6019.6 r270 top
U18 "HB9500M-9.5-05P-13-00A" CONN-TH_HB9500M-9.5-5P 6464.8,4583.7 r90 top
U19 "RH-5000" TEST-TH_BD2.54-P1.4_RED 6781.9,5781.1 r270 top
U20 "" SOT-23-5_L2.9-W1.7-P0.95-LS2.8-BL 4736.8,3656.9 r180 top
U21 "RH-5000" TEST-TH_BD2.54-P1.4_RED 4400.3,3094.7 r180 top
USB1 "TYPE-C 16PIN 2MD(073)" USB-C-SMD_TYPE-C-16PIN-2MD-073 3198.2,3507.4 r270 top locked
X1 "24MHz" CRYSTAL-SMD_4P-L2.0-W1.6-BL-A#1 5195.1,4394.8 r225 top
X2 "24MHz" CRYSTAL-SMD_4P-L2.0-W1.6-BL-A#2 4249.3,5315.2 r270 top

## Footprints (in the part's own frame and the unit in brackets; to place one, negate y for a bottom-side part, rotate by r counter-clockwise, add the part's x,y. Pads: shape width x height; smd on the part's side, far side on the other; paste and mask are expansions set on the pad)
01_HPM_Peripheral:FIX1 [mil]
  round 177.2 hole 137.8 paste+0 mask+0: 1(0,0)
02_HPM_Resistor:R_0402_1005Metric#1 [mil]
  rrect50% 21.3x25.2 smd paste+0 mask+0: 1(-20.1,0) 2(20.1,0)
  silkscreen extent -6,-15 6,15
02_HPM_Resistor:R_0402_1005Metric#2 [mil]
  rrect50% 21.3x25.2 smd paste+0 mask+0: 1(-20,0) 2(20.1,0)
  silkscreen extent -6,-15 6,15
02_HPM_Resistor:R_0402_1005Metric#3 [mil]
  rrect50% 21.3x25.2 smd paste+0 mask+0: 1(-20.1,0) 2(20,0)
  silkscreen extent -6,-15 6,15
02_HPM_Resistor:R_0603_1608Metric [mil]
  rrect50% 31.5x37.4 smd paste+0 mask+0: 1(-32.5,0) 2(32.5,0)
  silkscreen extent -9,-21 9,20
02_HPM_Resistor:R_1206_3216Metric#1 [mil]
  rrect50% 44.3x68.9 smd paste+0 mask+0: 1(-57.6,0) 2(57.6,0)
  silkscreen extent -29,-36 29,36
02_HPM_Resistor:R_1206_3216Metric#2 [mil]
  rrect50% 44.3x68.9 smd paste+0 mask+0: 1(-57.6,0) 2(57.5,0)
  silkscreen extent -29,-36 29,36
02_HPM_Resistor:R_1206_3216Metric#3 [mil]
  rrect44% 44.3x68.9 smd paste+0 mask+0: 1(-57.6,0) 2(57.6,0)
  silkscreen extent -29,-36 29,36
03_HPM_Capacitance:C_0402_1005Metric#1 [mil]
  round 23.6 smd paste+0 mask+0: 1(-18.81,0) 2(18.95,0)
  silkscreen extent -4,-14 4,14
03_HPM_Capacitance:C_0402_1005Metric#2 [mil]
  round 23.6 smd paste+0 mask+0: 1(-18.88,0.07) 2(18.95,0)
  silkscreen extent -4,-14 4,14
03_HPM_Capacitance:C_0402_1005Metric#3 [mil]
  round 23.6 smd paste+0 mask+0: 1(-18.9,0) 2(18.9,0)
  silkscreen extent -4,-14 4,14
03_HPM_Capacitance:C_0402_1005Metric#4 [mil]
  round 23.6 smd paste+0 mask+0: 1(-18.8,0) 2(18.9,0)
  silkscreen extent -4,-14 4,14
03_HPM_Capacitance:C_0402_1005Metric#5 [mil]
  round 23.6 smd paste+0 mask+0: 1(-18.9,0) 2(18.8,0)
  silkscreen extent -4,-14 4,14
03_HPM_Capacitance:C_0603_1608Metric#1 [mil]
  round 37.4 smd paste+0 mask+0: 1(-30.5,0) 2(30.5,0)
  silkscreen extent -6,-20 6,20
03_HPM_Capacitance:C_0603_1608Metric#2 [mil]
  round 37.4 smd paste+0 mask+0: 1(-30.5,0) 2(30.6,0)
  silkscreen extent -6,-20 6,20
03_HPM_Capacitance:C_0603_1608Metric#3 [mil]
  round 37.4 smd paste+0 mask+0: 1(-30.6,0) 2(30.5,0)
  silkscreen extent -6,-20 6,20
03_HPM_Capacitance:C_1206_3216Metric#1 [mil]
  rrect43% 45.3x70.9 smd paste+0 mask+0: 1(-58.1,0) 2(58,0)
  silkscreen extent -28,-36 28,36
03_HPM_Capacitance:C_1206_3216Metric#2 [mil]
  rrect50% 45.3x70.9 smd paste+0 mask+0: 1(-58.1,0) 2(58.1,0)
  silkscreen extent -28,-36 28,36
03_HPM_Capacitance:C_1206_3216Metric#3 [mil]
  rrect50% 45.3x70.9 smd paste+0 mask+0: 1(-58,0) 2(58.1,0)
  silkscreen extent -28,-36 28,36
03_HPM_Capacitance:C_1206_3216Metric#4 [mil]
  rrect43% 45.3x70.9 smd paste+0 mask+0: 1(-58.1,0) 2(58.1,0)
  silkscreen extent -28,-36 28,36
CABGA-121_L9.0-W9.0-R11-C11-P0.80-TL [mil]
  round 12.6 smd paste-3937 mask+2: A1(-157.47,157.47) A2(-126.01,157.54) A3(-94.47,157.54) A4(-63,157.47) A5(-31.54,157.54) A6(0,157.54) A7(31.47,157.47) A8(63,157.47) A9(94.47,157.54) A10(126.01,157.54) A11(157.47,157.47) B1(-157.54,126.01) B2(-126.01,126.01) B3(-94.47,126.01) B4(-63,126.08) B5(-31.54,126.01) B6(0,126.01) B7(31.54,126.01) B8(62.93,126.01) B9(94.47,126.01) B10(126.01,126.01) B11(157.47,126.08) C1(-157.47,94.54) C2(-126.01,94.47) C3(-94.54,94.54) C4(-63,94.54) C5(-31.47,94.54) C6(0,94.47) C7(31.47,94.54) C8(63,94.54) C9(94.47,94.47) C10(125.94,94.54) C11(157.47,94.54) D1(-157.47,63) D2(-126.01,63.07) D3(-94.54,63) D4(-63,63) D5(-31.47,63) D6(0,63.07) D7(31.47,63) D8(63,63) D9(94.47,63.07) D10(125.94,63) D11(157.47,63) E1(-157.54,31.54) E2(-126.01,31.54) E3(-94.47,31.54) E4(-63,31.47) E5(-31.54,31.54) E6(0,31.54) E7(31.54,31.54) E8(62.93,31.54) E9(94.47,31.54) E10(126.01,31.54) E11(157.4,31.54) F1(-157.47,0.07) F2(-126.01,0) F3(-94.47,0) F4(-63,0.07) F5(-31.54,0) F6(0,0) F7(31.47,0.07) F8(63,0.07) F9(94.47,0) F10(125.94,0.07) F11(157.47,0.07) G1(-157.47,-31.47) G2(-125.94,-31.47) G3(-94.54,-31.47) G4(-63,-31.47) G5(-31.47,-31.47) G6(-0.07,-31.47) G7(31.47,-31.47) G8(63,-31.47) G9(94.54,-31.47) G10(125.94,-31.47) G11(157.47,-31.47) H1(-157.47,-63) H2(-126.01,-62.93) H3(-94.47,-62.93) H4(-63,-63) H5(-31.54,-62.93) H6(0,-62.93) H7(31.47,-63) H8(62.93,-62.93) H9(94.47,-62.93) H10(126.01,-62.93) H11(157.47,-63) J1(-157.54,-94.47) J2(-126.01,-94.47) J3(-94.47,-94.47) J4(-63,-94.4) J5(-31.54,-94.47) J6(0,-94.47) J7(31.54,-94.47) J8(62.93,-94.47) J9(94.47,-94.47) J10(126.01,-94.47) J11(157.47,-94.4) K1(-157.47,-125.94) K2(-125.94,-125.94) K3(-94.54,-125.94) K4(-63,-125.94) K5(-31.47,-125.94) K6(-0.07,-125.94) K7(31.47,-125.94) K8(63,-125.94) K9(94.47,-126.01) K10(125.94,-125.94) K11(157.47,-125.94) L1(-157.47,-157.47) L2(-126.01,-157.4) L3(-94.54,-157.47) L4(-63,-157.47) L5(-31.54,-157.4) L6(0,-157.4) L7(31.47,-157.47) L8(63,-157.47) L9(94.47,-157.4) L10(125.94,-157.47) L11(157.47,-157.47)
  silkscreen extent -196,-196 196,196
CAP-TH_BD8.0-P3.50-D0.6-FD [mil]
  round 63 hole 39.4: 1(-68.9,0) 2(68.9,0)
  silkscreen extent -156,-157 159,158
CONN-TH_HB9500M-9.5-5P [mil]
  rect 126.4x126 hole 78.7: 1(-748,0)
  round 126 hole 78.7: 2(-374,0) 3(0,0) 4(374,0) 5(748,0)
  silkscreen extent -964,-475 965,155
CONN-TH_XY2500R-G-3.5-3P [mil]
  round 78.7 hole 51.2: 1(-137.8,0) 2(0,0) 3(137.8,0)
  silkscreen extent -226,-303 226,55
CONN-TH_XY2500R-G-3.5-4P [mil]
  round 78.7 hole 51.2: 1(-206.7,0) 2(-68.9,0) 3(68.9,0) 4(206.7,0)
  silkscreen extent -295,-303 295,55
CONN-TH_XY2500R-G-3.5-5P [mil]
  round 86.6 hole 55.1: 1(-275.6,0) 2(-137.8,0) 3(0,0) 4(137.8,0) 5(275.6,0)
  silkscreen extent -364,-55 364,303
CONN-TH_XY2500R-G-3.5-6P [mil]
  round 86.6 hole 55.1: 1(-344.4,0) 2(-206.7,0) 3(-68.9,0) 4(68.9,0) 5(206.7,0) 6(344.5,0)
  silkscreen extent -433,-55 433,303
CRYSTAL-SMD_4P-L2.0-W1.6-BL-A#1 [mil]
  rect 34.4x30.5 smd: 1(-25.03,-19.23) 2(25.24,-19.16) 3(25.24,19.16) 4(-25.03,19.23)
  silkscreen extent -49,-40 -25,-19
CRYSTAL-SMD_4P-L2.0-W1.6-BL-A#2 [mil]
  rect 34.4x30.5 smd: 1(-25.1,-19.2) 2(25.2,-19.2) 3(25.2,19.2) 4(-25.1,19.2)
  silkscreen extent -49,-40 -25,-19
ESOP-8_L4.9-W3.9-P1.27-LS6.0-BL-EP-1 [mil]
  oval 24.8x73.4 smd: 1(-75,-105.6) 2(-25,-105.6) 3(25,-105.6) 4(75,-105.6) 5(75,105.6) 6(25,105.6) 7(-25,105.6) 8(-75,105.6)
  rect 129.9x94.5 smd paste+0 mask+2: 9(0,0)
  silkscreen extent -111,-111 101,60
FILTER-SMD_4P-L2.0-W1.2-BL_DLW21H [mil]
  rect 15.7x29.5 smd: 1(-15.8,-36.4) 2(-15.8,36.5) 3(15.7,36.5) 4(15.7,-36.4)
  silkscreen extent -34,-39 33,39
FILTER-SMD_4P-L2.5-W2.0-BL [mil]
  rect 29.3x24.8 smd: 1(-45.1,25.5) 2(-45.1,-25.6) 3(45.2,-25.6) 4(45.2,25.5)
  silkscreen extent -52,-42 52,42
IDC-TH_10P-P2.54_C5665 [mil]
  round 60 hole 39.4 paste+0 mask+2: 1(-200,-50) 2(-200,50) 3(-100,-50) 4(-100,50) 5(0,-50) 6(0,50) 7(100,-50) 8(100,50) 9(200,-50) 10(200,50)
  silkscreen extent -400,-175 400,173
IND-SMD_L2.5-W2.0-VLS252012CX-150M#1 [mil]
  rect 33.5x78.7 smd: 1(-32.7,0) 2(32.7,0)
  silkscreen extent -11,-43 11,43
IND-SMD_L2.5-W2.0-VLS252012CX-150M#2 [mil]
  rect 33.5x78.7 smd: 1(-32.6,0) 2(32.7,0)
  silkscreen extent -11,-43 11,43
IND-SMD_L4.6-W4.2_SMMS0420 [mil]
  rect 55.1x74.8 smd: 1(80,0) 2(-80,0)
  silkscreen extent -94,-88 94,88
LGA-25_L6.5-W5.0-P0.85-TL#1 [mil]
  rect 23.6x13.8 smd: 1(-80,74.7) 2(-80,41.3) 23(80,41.3) 24(80,74.7)
  round 25.6 smd: 3(0,-1.2)
  round 31.3 smd: 5(0.2,-58.3)
  round 16.8 smd: 9(0.2,-109.9)
  rect 13.8x23.6 smd: 25(83.6,109.9) 26(50.2,109.9) 27(16.7,109.9) 28(-16.8,109.9) 29(-50.2,109.9) 30(-83.7,109.9)
  Top Layer region: -92.9,-124.9 -92.9,-99.7 93.3,-99.7 93.3,-124.9 83.8,-124.9 83.8,-119.7 73.6,-119.7 73.6,-124.9 64.1,-124.9 64.1,-120.1 54.3,-120.1 54.3,-124.9 44.5,-124.9 44.5,-120.1 34.2,-120.1 34.2,-124.9 24.8,-124.9 24.8,-120.1 14.5,-120.1 14.5,-124.9 5.1,-124.9 5.1,-120.1 -4.4,-120.1 -4.4,-124.9 -14.6,-124.9 -14.6,-120.1 -24.4,-120.1 -24.4,-124.9 -34.3,-124.9 -34.3,-120.1 -44.1,-120.1 -44.1,-124.9 -54,-124.9 -54,-120.1 -63.4,-120.1 -63.4,-124.9 -73.3,-124.9 -73.3,-120.1 -83.1,-120.1 -83.1,-124.9
  Top Layer region: -95.7,-39.4 -87.8,-39.4 -87.8,-36.7 90.1,-36.7 90.1,-39.4 95.6,-39.4 95.6,-46.5 90.1,-46.5 90.1,-54.8 96,-54.8 96,-62.7 90.1,-62.7 90.1,-70.5 96,-70.5 96,-77.6 90.1,-77.6 90.1,-80 -87.8,-80 -87.8,-78 -95.7,-78 -95.7,-70.1 -90.2,-70.1 -90.2,-61.9 -95.7,-61.9 -95.7,-54.8 -90.2,-54.8 -90.2,-46.9 -95.7,-46.9
  Top Layer region: -95.7,10.6 -89.4,10.6 -89.4,14.9 91.3,14.9 91.3,10.6 95.2,10.6 95.2,3.1 91.3,3.1 91.3,-5.2 95.6,-5.2 95.6,-12.7 90.5,-12.7 90.5,-17.4 -89.4,-17.4 -89.4,-12.7 -95.7,-12.7 -95.7,-5.2 -89.4,-5.2 -89.4,2.3 -95.7,2.3
  silkscreen extent -106,-135 106,148
LGA-25_L6.5-W5.0-P0.85-TL#2 [mil]
  rect 23.6x13.8 smd: 1(-80,74.7) 2(-80,41.3) 23(80,41.3) 24(80,74.7)
  round 25.6 smd: 3(0,-1.2)
  round 31.3 smd: 5(0.1,-58.3)
  round 16.8 smd: 9(0.1,-109.9)
  rect 13.8x23.6 smd: 25(83.6,109.9) 26(50.1,109.9) 27(16.7,109.9) 28(-16.8,109.9) 29(-50.2,109.9) 30(-83.7,109.9)
  Top Layer region: -93,-124.9 -93,-99.7 93.3,-99.7 93.3,-124.9 83.8,-124.9 83.8,-119.7 73.6,-119.7 73.6,-124.9 64.1,-124.9 64.1,-120.1 54.3,-120.1 54.3,-124.9 44.4,-124.9 44.4,-120.1 34.2,-120.1 34.2,-124.9 24.8,-124.9 24.8,-120.1 14.5,-120.1 14.5,-124.9 5.1,-124.9 5.1,-120.1 -4.4,-120.1 -4.4,-124.9 -14.6,-124.9 -14.6,-120.1 -24.5,-120.1 -24.5,-124.9 -34.3,-124.9 -34.3,-120.1 -44.1,-120.1 -44.1,-124.9 -54,-124.9 -54,-120.1 -63.4,-120.1 -63.4,-124.9 -73.3,-124.9 -73.3,-120.1 -83.1,-120.1 -83.1,-124.9
  Top Layer region: -95.7,-39.4 -87.8,-39.4 -87.8,-36.7 90.1,-36.7 90.1,-39.4 95.6,-39.4 95.6,-46.5 90.1,-46.5 90.1,-54.8 96,-54.8 96,-62.7 90.1,-62.7 90.1,-70.5 96,-70.5 96,-77.6 90.1,-77.6 90.1,-80 -87.8,-80 -87.8,-78 -95.7,-78 -95.7,-70.1 -90.2,-70.1 -90.2,-61.9 -95.7,-61.9 -95.7,-54.8 -90.2,-54.8 -90.2,-46.9 -95.7,-46.9
  Top Layer region: -95.7,10.6 -89.4,10.6 -89.4,14.9 91.3,14.9 91.3,10.6 95.2,10.6 95.2,3.1 91.3,3.1 91.3,-5.2 95.6,-5.2 95.6,-12.7 90.5,-12.7 90.5,-17.4 -89.4,-17.4 -89.4,-12.7 -95.7,-12.7 -95.7,-5.2 -89.4,-5.2 -89.4,2.3 -95.7,2.3
  silkscreen extent -106,-135 106,148
LGA-25_L6.5-W5.0-P0.85-TL#3 [mil]
  rect 23.6x13.8 smd: 1(-80,74.7) 2(-80,41.3) 23(80,41.3) 24(80,74.7)
  round 25.6 smd: 3(0,-1.2)
  round 31.3 smd: 5(0.2,-58.3)
  round 16.8 smd: 9(0.2,-109.9)
  rect 13.8x23.6 smd: 25(83.7,109.9) 26(50.2,109.9) 27(16.8,109.9) 28(-16.7,109.9) 29(-50.2,109.9) 30(-83.6,109.9)
  Top Layer region: -92.9,-124.9 -92.9,-99.7 93.3,-99.7 93.3,-124.9 83.9,-124.9 83.9,-119.7 73.7,-119.7 73.7,-124.9 64.2,-124.9 64.2,-120.1 54.4,-120.1 54.4,-124.9 44.5,-124.9 44.5,-120.1 34.3,-120.1 34.3,-124.9 24.8,-124.9 24.8,-120.1 14.6,-120.1 14.6,-124.9 5.2,-124.9 5.2,-120.1 -4.3,-120.1 -4.3,-124.9 -14.5,-124.9 -14.5,-120.1 -24.4,-120.1 -24.4,-124.9 -34.2,-124.9 -34.2,-120.1 -44.1,-120.1 -44.1,-124.9 -53.9,-124.9 -53.9,-120.1 -63.3,-120.1 -63.3,-124.9 -73.2,-124.9 -73.2,-120.1 -83,-120.1 -83,-124.9
  Top Layer region: -95.6,-39.4 -87.8,-39.4 -87.8,-36.7 90.2,-36.7 90.2,-39.4 95.7,-39.4 95.7,-46.5 90.2,-46.5 90.2,-54.8 96.1,-54.8 96.1,-62.7 90.2,-62.7 90.2,-70.5 96.1,-70.5 96.1,-77.6 90.2,-77.6 90.2,-80 -87.8,-80 -87.8,-78 -95.6,-78 -95.6,-70.1 -90.1,-70.1 -90.1,-61.9 -95.6,-61.9 -95.6,-54.8 -90.1,-54.8 -90.1,-46.9 -95.6,-46.9
  Top Layer region: -95.6,10.6 -89.3,10.6 -89.3,14.9 91.4,14.9 91.4,10.6 95.3,10.6 95.3,3.1 91.4,3.1 91.4,-5.2 95.7,-5.2 95.7,-12.7 90.6,-12.7 90.6,-17.4 -89.3,-17.4 -89.3,-12.7 -95.6,-12.7 -95.6,-5.2 -89.3,-5.2 -89.3,2.3 -95.6,2.3
  silkscreen extent -106,-135 106,148
QFN-48_L6.0-W6.0-P0.40-BL-EP3.8 [mil]
  rect 7.9x26.2 smd paste-3937 mask+2: 1(-86.6,-114.5) 2(-70.9,-114.5) 3(-55.1,-114.5) 4(-39.4,-114.5) 5(-23.6,-114.5) 6(-7.9,-114.5) 7(7.9,-114.5) 8(23.6,-114.5) 9(39.4,-114.5) 10(55.1,-114.5) 11(70.9,-114.5) 12(86.6,-114.5) 25(86.6,114.5) 26(70.9,114.5) 27(55.1,114.5) 28(39.4,114.5) 29(23.6,114.5) 30(7.9,114.5) 31(-7.9,114.5) 32(-23.6,114.5) 33(-39.4,114.5) 34(-55.1,114.5) 35(-70.9,114.5) 36(-86.6,114.5)
  rect 26.2x7.9 smd paste-3937 mask+2: 13(114.5,-86.6) 14(114.5,-70.9) 15(114.5,-55.1) 16(114.5,-39.4) 17(114.5,-23.6) 18(114.5,-7.9) 19(114.5,7.9) 20(114.5,23.6) 21(114.5,39.4) 22(114.5,55.1) 23(114.5,70.9) 24(114.5,86.6) 37(-114.5,86.6) 38(-114.5,70.9) 39(-114.5,55.1) 40(-114.5,39.4) 41(-114.5,23.6) 42(-114.5,7.9) 43(-114.5,-7.9) 44(-114.5,-23.6) 45(-114.5,-39.4) 46(-114.5,-55.1) 47(-114.5,-70.9) 48(-114.5,-86.6)
  rect 149.6x149.6 smd paste-3937 mask+2: 49(0,0)
  silkscreen extent -121,-142 121,121
RES-ARRAY-SMD_8P-L2.0-W1.0-BL_CN24XXXX [mil]
  rect 15.7x19.9 smd: 1(-31.5,16.8) 4(31.5,16.8) 5(31.5,-16.9) 8(-31.5,-16.9)
  rect 11.8x19.9 smd: 2(-9.8,16.8) 3(9.9,16.8) 6(9.9,-16.9) 7(-9.8,-16.9)
  silkscreen extent -39,0 39,0
RES-SMD_4P-L3.0-W3.8_HOBB1216#1 [mil]
  rect 59.1x116.1 smd: 1(-41.4,-45.8) 2(41.3,-45.8)
  rect 59.1x27.6 smd: 3(-41.4,45.8) 4(41.3,45.8)
  silkscreen extent -80,-115 80,70
RES-SMD_4P-L3.0-W3.8_HOBB1216#2 [mil]
  rect 59.1x116.1 smd: 1(-41.4,-45.7) 2(41.3,-45.7)
  rect 59.1x27.6 smd: 3(-41.4,45.8) 4(41.3,45.8)
  silkscreen extent -80,-115 80,70
RJ45-TH_HR911130A [mil]
  round 66.9 hole 43.3: 11(260.8,271.4) 12(160.8,271.4) 13(-160.8,271.4) 14(-260.8,271.4)
  rect 60x60 hole 35.8: P1(225.2,-271.5)
  round 60 hole 35.8: P2(179.1,-171.5) P3(125.2,-271.5) P4(79.1,-171.5) P5(25.2,-271.5) P6(-20.9,-171.5) P7(-74.8,-271.5) P8(-120.9,-171.5) P9(-174.8,-271.5) P10(-220.9,-171.5)
  round 85 hole 66.9: SHIELD0(-304.9,-41.6) SHIELD1(304.9,-41.6)
  Board Outline Layer circle w0.1: c-225,78.5 r64
  Board Outline Layer circle w0.1: c225,78.5 r64
  Board Outline Layer region: -225,14.5 -252.77,20.84 -275.04,38.6 -287.4,64.26 -287.4,92.74 -275.04,118.4 -252.77,136.16 -225,142.5 -225,142.5 -197.23,136.16 -174.96,118.4 -162.6,92.74 -162.6,64.26 -174.96,38.6 -197.23,20.84 -225,14.5
  Board Outline Layer region: -225,14.5 -252.77,20.84 -275.04,38.6 -287.4,64.26 -287.4,92.74 -275.04,118.4 -252.77,136.16 -225,142.5 -225,142.5 -197.23,136.16 -174.96,118.4 -162.6,92.74 -162.6,64.26 -174.96,38.6 -197.23,20.84 -225,14.5
  Board Outline Layer region: 225,14.5 197.23,20.84 174.96,38.6 162.6,64.26 162.6,92.74 174.96,118.4 197.23,136.16 225,142.5 225,142.5 252.77,136.16 275.04,118.4 287.4,92.74 287.4,64.26 275.04,38.6 252.77,20.84 225,14.5
  Board Outline Layer region: 225,14.5 197.23,20.84 174.96,38.6 162.6,64.26 162.6,92.74 174.96,118.4 197.23,136.16 225,142.5 225,142.5 252.77,136.16 275.04,118.4 287.4,92.74 287.4,64.26 275.04,38.6 252.77,20.84 225,14.5
  silkscreen extent -316,-331 316,508
RJ45-TH_J8064D628ANL [mil]
  round 55 hole 35 slot 35.2 at 0 deg paste+0 mask+2: A1(-450,127.4) A2(-400,227.4) A3(-350,127.4) A4(-296.1,227.4) A5(-250,127.4) A6(-200,227.4) A7(-150,127.4) A8(-100,227.4) B1(100,127.4) B2(150,227.4) B3(200,127.4) B4(250,227.4) B5(300,127.4) B6(350,227.4) B7(400,127.4) B8(450,227.4)
  round 60.2 hole 40.2 slot 40.4 at 0 deg paste+0 mask+2: A9(-530.3,-282.5) A10(-430.3,-282.5) A11(-119.7,-282.5) A12(-20.1,-282.5) B9(20.1,-212.8) B10(119.7,-212.8) B11(430.3,-282.5) B12(530.3,-282.5)
  round 92.7 hole 61.8 paste+0 mask+2: S1(-608.9,-2.6) S2(608.9,-2.6) S3(0,282.5)
  Board Outline Layer circle w0.1: c500,-122.6 r63
  Board Outline Layer circle w0.1: c-500,-122.6 r63
  Board Outline Layer region: 500,-59.6 527.33,-65.84 549.26,-83.32 561.42,-108.58 561.42,-136.62 549.26,-161.88 527.33,-179.36 500,-185.6 500,-185.6 472.67,-179.36 450.74,-161.88 438.58,-136.62 438.58,-108.58 450.74,-83.32 472.67,-65.84 500,-59.6
  Board Outline Layer region: 500,-59.6 527.33,-65.84 549.26,-83.32 561.42,-108.58 561.42,-136.62 549.26,-161.88 527.33,-179.36 500,-185.6 500,-185.6 472.67,-179.36 450.74,-161.88 438.58,-136.62 438.58,-108.58 450.74,-83.32 472.67,-65.84 500,-59.6
  Board Outline Layer region: -500,-59.6 -472.67,-65.84 -450.74,-83.32 -438.58,-108.58 -438.58,-136.62 -450.74,-161.88 -472.67,-179.36 -500,-185.6 -500,-185.6 -527.33,-179.36 -549.26,-161.88 -561.42,-136.62 -561.42,-108.58 -549.26,-83.32 -527.33,-65.84 -500,-59.6
  Board Outline Layer region: -500,-59.6 -472.67,-65.84 -450.74,-83.32 -438.58,-108.58 -438.58,-136.62 -450.74,-161.88 -472.67,-179.36 -500,-185.6 -500,-185.6 -527.33,-179.36 -549.26,-161.88 -561.42,-136.62 -561.42,-108.58 -549.26,-83.32 -527.33,-65.84 -500,-59.6
  silkscreen extent -665,-547 666,294
SMAF_L3.5-W2.6-LS4.7-RD-1 [mil]
  rect 63x66.9 smd: 1(-77.2,0) 2(77.1,0)
  silkscreen extent -79,-56 72,56
SOT-23-3_L2.9-W1.3-P1.90-LS2.4-BL-2 [mil]
  rect 27.6x49.2 smd: 1(-37.4,-39.4) 2(37.4,-39.4) 3(0,39.3)
  silkscreen extent -60,-29 60,29
SOT-23-5_L2.9-W1.7-P0.95-LS2.8-BL [mil]
  rect 23.6x39.4 smd: 1(-37.4,-51.2) 2(0,-51.2) 3(37.4,-51.2) 4(37.4,51.1) 5(-37.4,51.1)
  silkscreen extent -70,-65 61,35
SOT-23-5_L3.0-W1.7-P0.95-LS2.8-BL [mil]
  rect 19.3x45.6 smd: 1(-37.4,-45.5) 2(0,-45.5) 3(37.4,-45.5)
  rect 19.3x46.3 smd: 4(37.4,45.4) 5(-37.4,45.4)
  silkscreen extent -71,-51 60,34
SOT-23_L2.9-W1.3-P1.90-LS2.4-BR [mil]
  rect 39.4x31.5 smd: 1(45.3,-37.4) 2(45.3,37.4) 3(-45.2,0)
  silkscreen extent -28,-59 28,59
SOT-143-4_L2.9-W1.3-P1.92-LS2.4-BL [mil]
  rect 47x33 smd: 1(-29.5,-46.9)
  rect 33x33 smd: 2(37.4,-46.9) 3(37.4,46.9) 4(-37.4,46.9)
  silkscreen extent -74,-42 61,30
SOT-563_L1.6-W1.2-P0.50-LS1.6-TL#1 [mil]
  rect 19.7x11.8 smd: 1(-31.5,19.7) 2(-31.5,0) 3(-31.5,-19.6) 4(31.5,-19.6) 5(31.5,0) 6(31.5,19.7)
  silkscreen extent -35,-31 19,39
SOT-563_L1.6-W1.2-P0.50-LS1.6-TL#2 [mil]
  rect 19.7x11.8 smd: 1(-31.5,19.7) 2(-31.5,0) 3(-31.5,-19.7) 4(31.5,-19.7) 5(31.5,0) 6(31.5,19.7)
  silkscreen extent -35,-31 19,39
TDFN-8_L3.0-W3.0-P0.65-BL-EP2.3 [mil]
  rect 12.6x24.6 smd: 1(-38.3,-55.6) 2(-12.8,-55.6) 3(12.8,-55.6) 4(38.4,-55.6) 5(38.4,55.6) 6(12.8,55.6) 7(-12.8,55.6) 8(-38.3,55.6)
  rect 90.6x59.1 smd: 9(0,0)
  silkscreen extent -62,-79 62,62
TEST-TH_BD2.54-P1.4_RED [mil]
  round 74.8 hole 47.2: 1(0,0)
  silkscreen extent -50,-50 50,50
TSOT-23-6_L2.9-W1.6-P0.95-LS2.8-BL [mil]
  rect 21.7x47.2 smd: 1(-37.4,-47.3) 2(0,-47.3) 3(37.4,-47.3) 4(37.4,47.2) 5(0,47.2) 6(-37.4,47.2)
  silkscreen extent -59,-89 59,32
TSSOP-8_L4.4-W3.0-P0.65-LS6.4-BL#1 [mil]
  oval 13.9x57.2 smd: 1(-38.4,-115.2) 2(-12.8,-115.2) 3(12.8,-115.2) 4(38.4,-115.2) 5(38.4,115.2) 6(12.8,115.2) 7(-12.8,115.2) 8(-38.4,115.2)
  silkscreen extent -59,-76 59,77
TSSOP-8_L4.4-W3.0-P0.65-LS6.4-BL#2 [mil]
  oval 13.9x57.2 smd: 1(-38.4,-115.3) 2(-12.8,-115.3) 3(12.8,-115.3) 4(38.4,-115.3) 5(38.4,115.2) 6(12.8,115.2) 7(-12.8,115.2) 8(-38.4,115.2)
  silkscreen extent -59,-76 59,77
TSSOP-8_L4.4-W3.0-P0.65-LS6.4-BL#3 [mil]
  oval 13.9x57.2 smd: 1(-38.4,-115.2) 2(-12.8,-115.2) 3(12.8,-115.2) 4(38.4,-115.2) 5(38.4,115.3) 6(12.8,115.3) 7(-12.8,115.3) 8(-38.4,115.3)
  silkscreen extent -59,-76 59,77
USB-C-SMD_TYPE-C-16PIN-2MD-073 [mil]
  oval 43.3x78.7 hole 23.6 slot 59.1 at 90 deg paste+0 mask+2: 13(-170.2,71.9) 14(170.3,71.9)
  oval 47.2x70.9 hole 23.6 slot 47.2 at 90 deg paste+0 mask+2: 13(-170.2,-93.5) 14(170.3,-93.5)
  rect 21.7x43.3 smd paste+0 mask+2: A1B12(-125.9,93.5) A4B9(-94.4,93.5) B1A12(126,93.5) B4A9(94.5,93.5)
  rect 11.8x43.3 smd paste+0 mask+2: A5(-49.2,93.5) A6(-9.8,93.5) A7(9.9,93.5) A8(49.3,93.5) B5(68.9,93.5) B6(29.6,93.5) B7(-29.5,93.5) B8(-68.8,93.5)
  Board Outline Layer circle w0.1: c-113.7,51.4 r13.8
  Board Outline Layer circle w0.1: c113.8,51.4 r13.8
  Board Outline Layer region: -113.7,65.2 -107.71,63.83 -102.91,60 -100.25,54.47 -100.25,48.33 -102.91,42.8 -107.71,38.97 -113.7,37.6 -113.7,37.6 -119.69,38.97 -124.49,42.8 -127.15,48.33 -127.15,54.47 -124.49,60 -119.69,63.83 -113.7,65.2
  Board Outline Layer region: -113.7,65.2 -107.71,63.83 -102.91,60 -100.25,54.47 -100.25,48.33 -102.91,42.8 -107.71,38.97 -113.7,37.6 -113.7,37.6 -119.69,38.97 -124.49,42.8 -127.15,48.33 -127.15,54.47 -124.49,60 -119.69,63.83 -113.7,65.2
  Board Outline Layer region: 113.8,65.2 119.79,63.83 124.59,60 127.25,54.47 127.25,48.33 124.59,42.8 119.79,38.97 113.8,37.6 113.8,37.6 107.81,38.97 103.01,42.8 100.35,48.33 100.35,54.47 103.01,60 107.81,63.83 113.8,65.2
  Board Outline Layer region: 113.8,65.2 119.79,63.83 124.59,60 127.25,54.47 127.25,48.33 124.59,42.8 119.79,38.97 113.8,37.6 113.8,37.6 107.81,38.97 103.01,42.8 100.35,48.33 100.35,54.47 103.01,60 107.81,63.83 113.8,65.2
  silkscreen extent -177,-196 180,24

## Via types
v1: diameter 17.7, hole 12, Top Layer to Bottom Layer, 133 vias
v2: diameter 24, hole 12, Top Layer to Bottom Layer, 4 vias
